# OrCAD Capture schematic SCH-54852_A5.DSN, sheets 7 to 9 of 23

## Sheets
7 C-15 M.2: size C
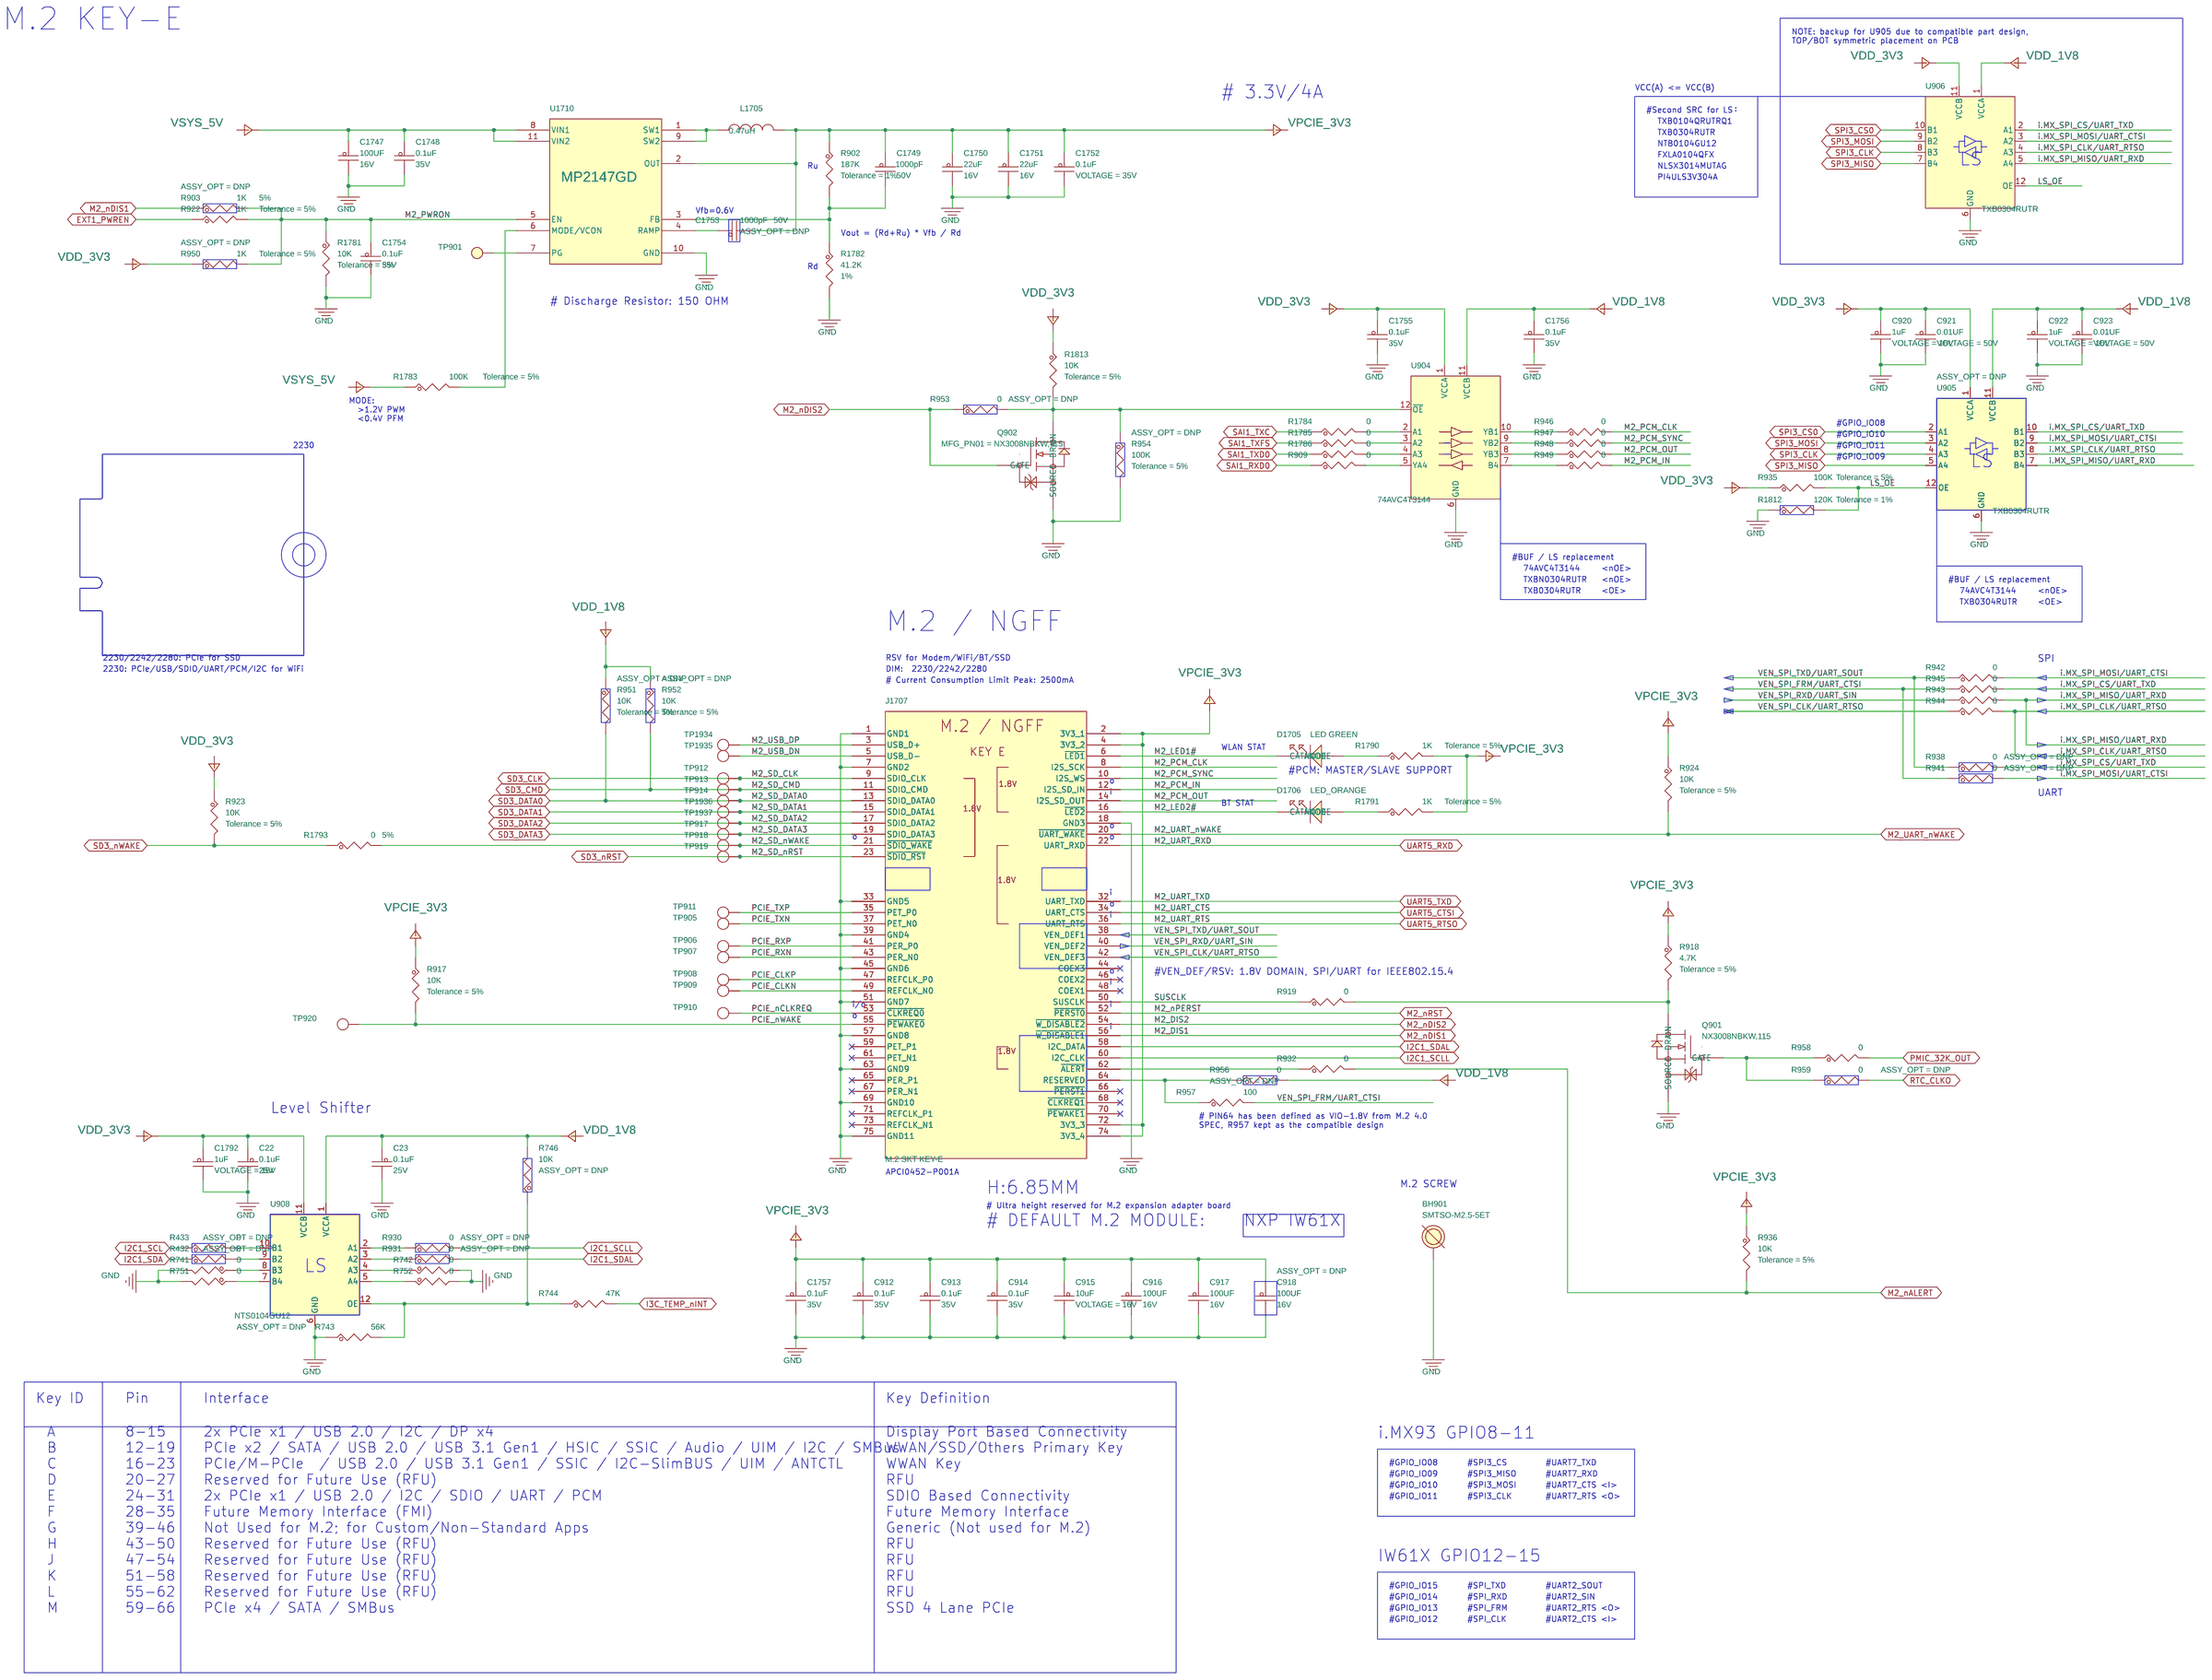
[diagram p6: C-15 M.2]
8 C-14 ENET1: size C
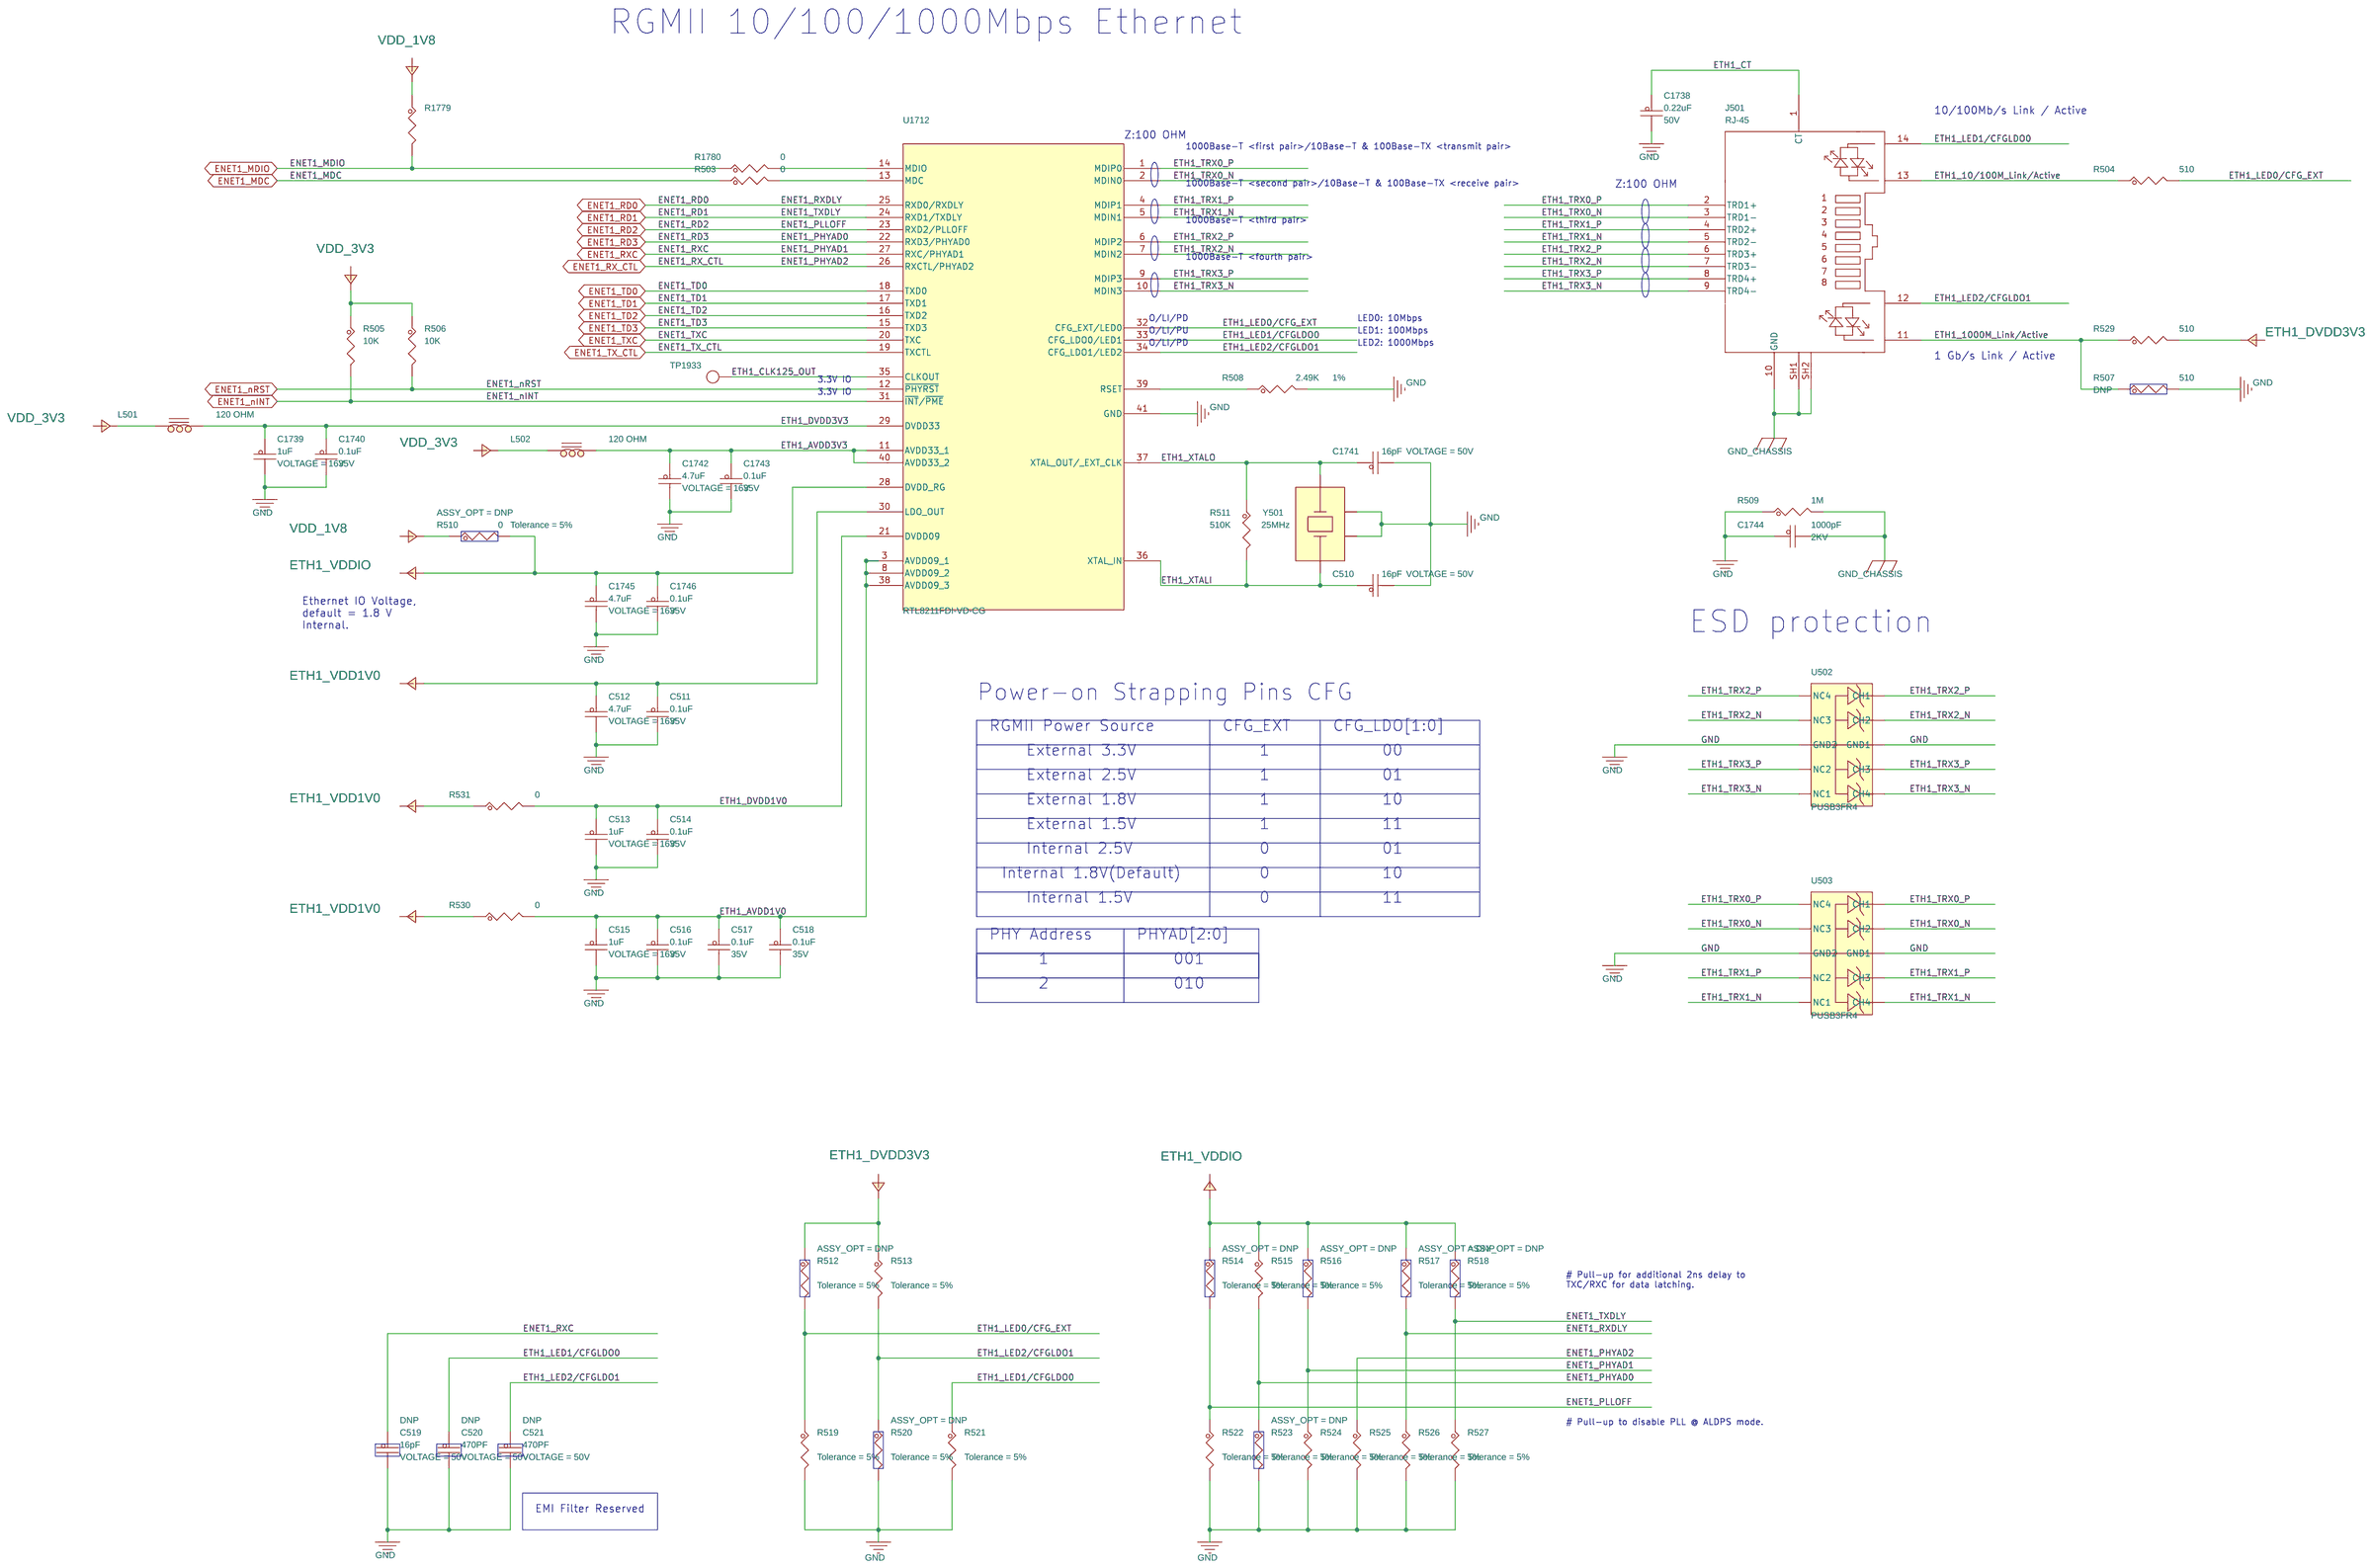
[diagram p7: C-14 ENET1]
9 C-13 USB1 C: size C
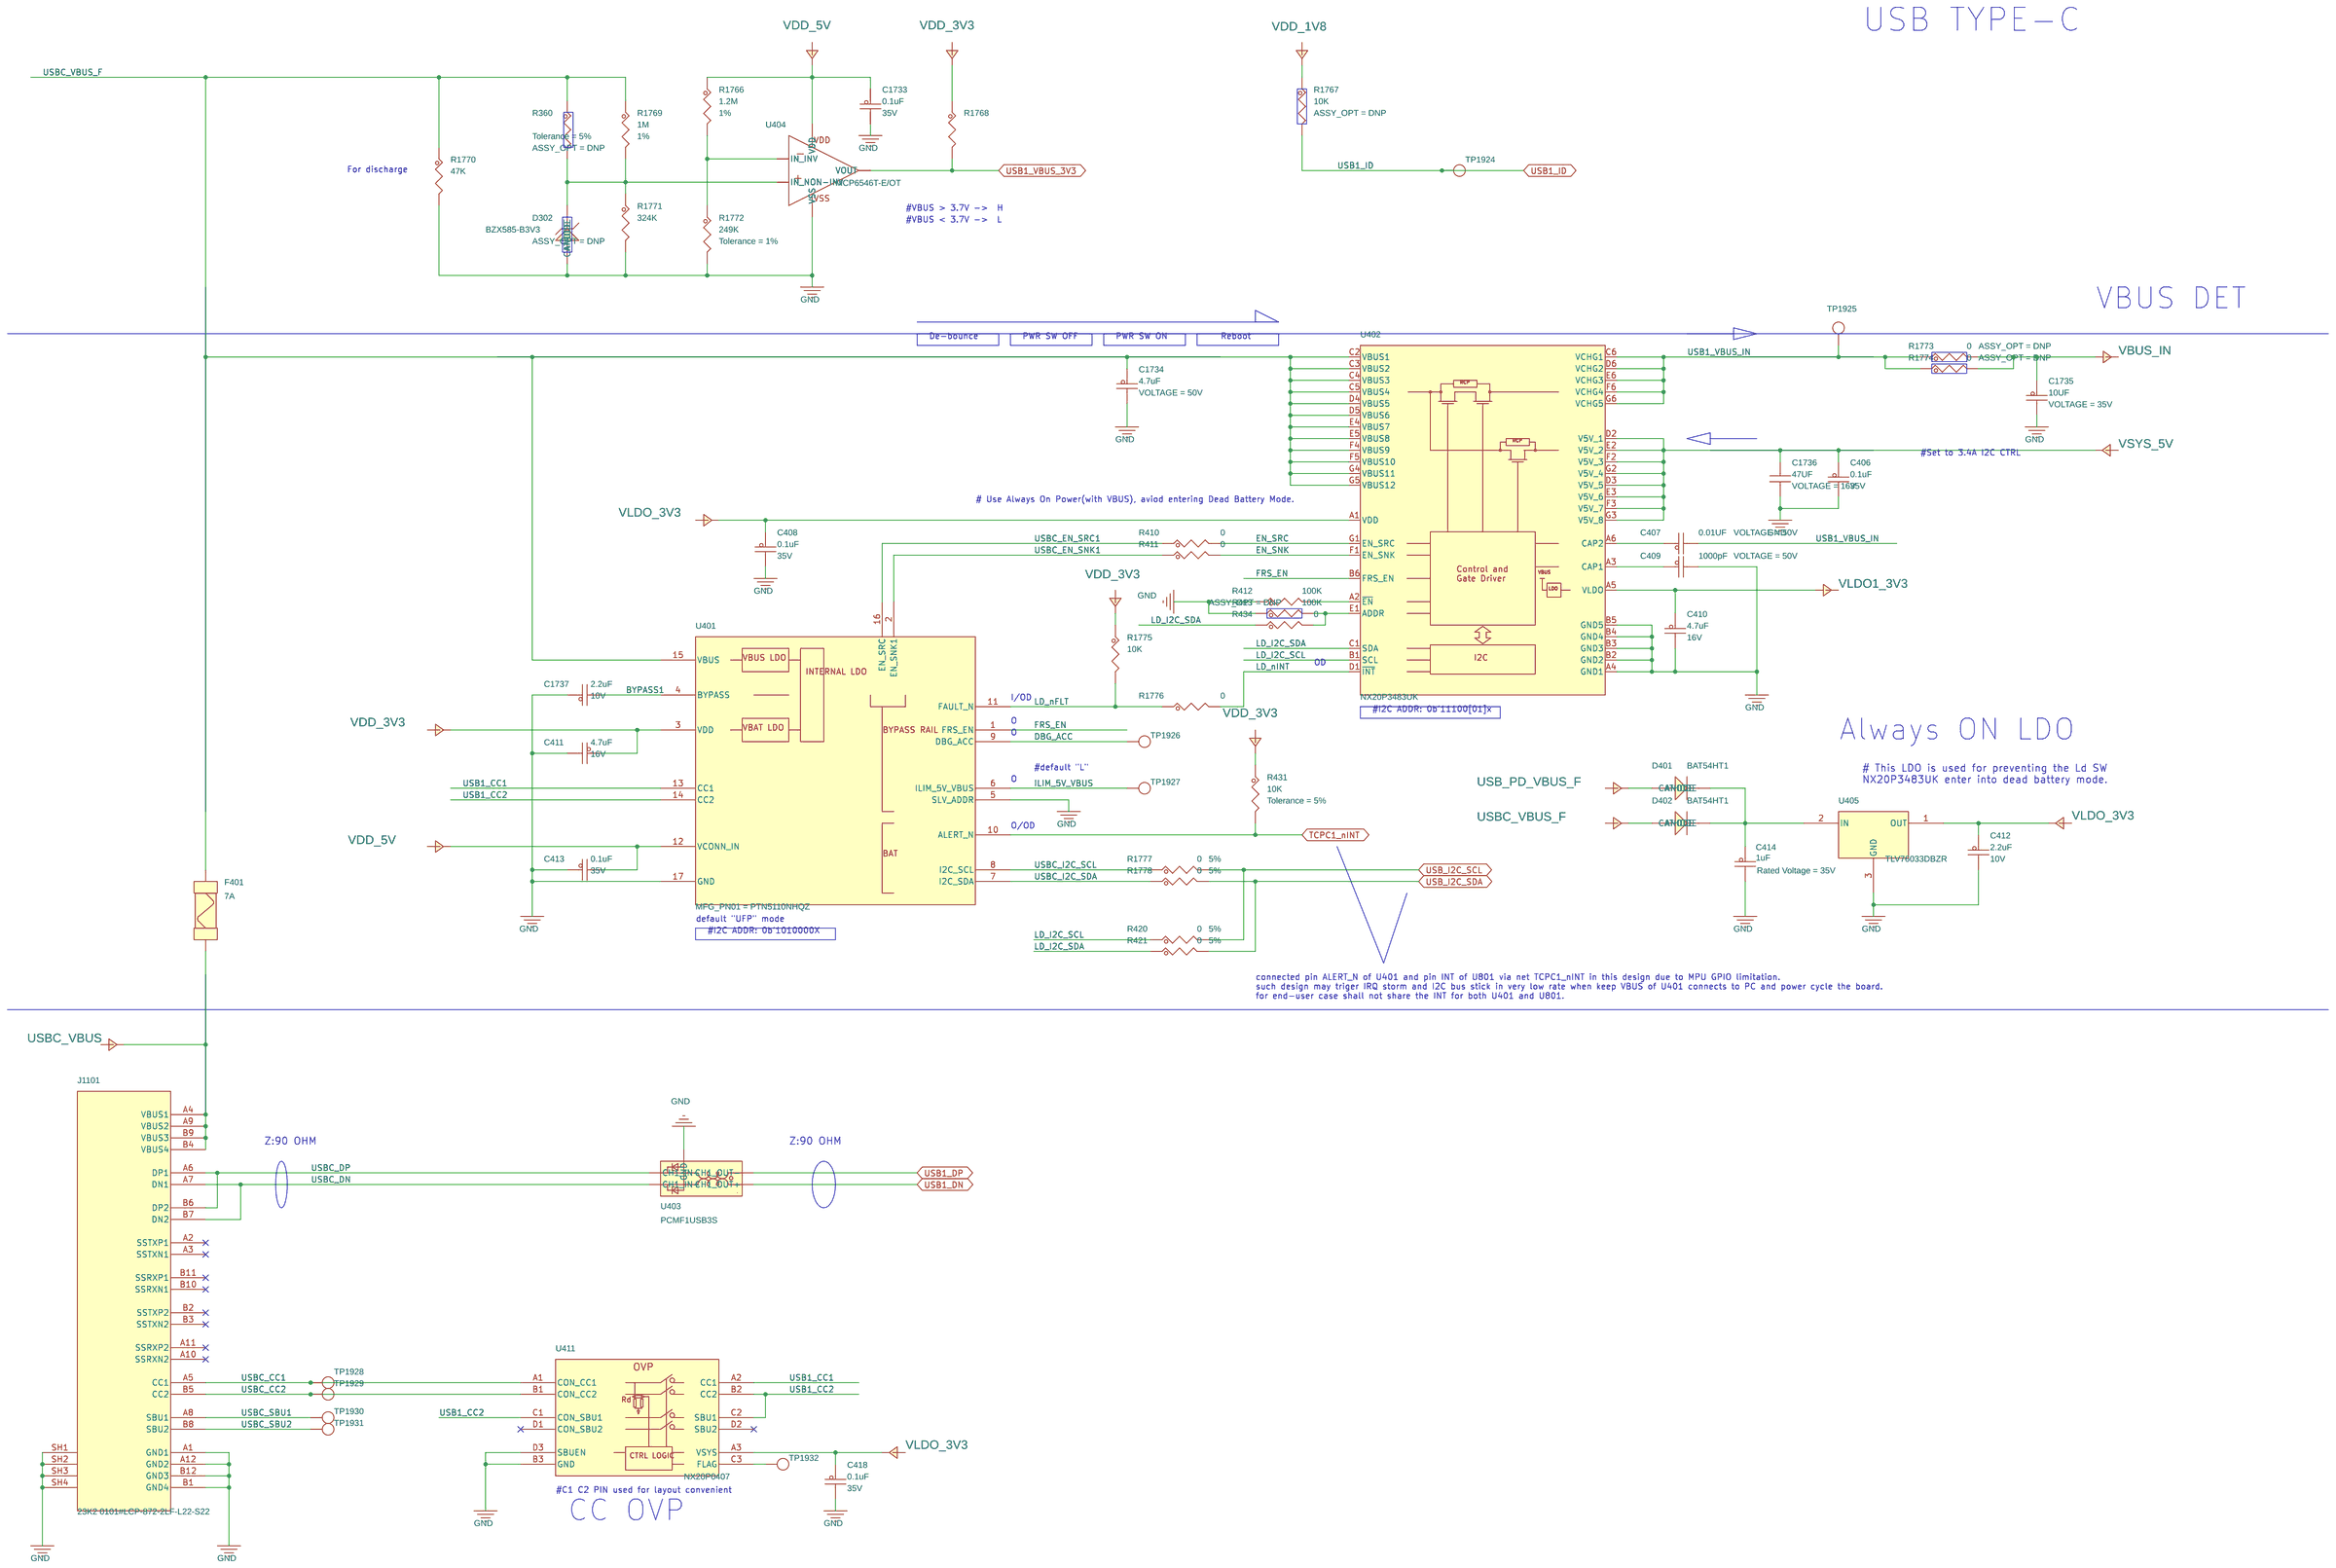
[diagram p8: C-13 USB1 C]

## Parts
sheet C-13 USB1 C
C406  0.1uF  [CC0402_25]
C407  0.01UF  [0402_CC]
C408  0.1uF  [CC0402_25]
C409  1000pF  [0402_CC]
C410  4.7uF  [CC0603_OV]
C411  4.7uF  [CC0603_OV]
C412  2.2uF  [0402_CC]
C413  0.1uF  [CC0402_25]
C414  1uF  [CC0603_OV]
C418  0.1uF  [CC0402_25]
C1733  0.1uF  [CC0402_25]
C1734  4.7uF  [CC1210]
C1735  10UF  [CC1210]
C1736  47UF  [CC1210]
C1737  2.2uF  [0402_CC]
D302  BZX585-B3V3  [sod523]
D401  BAT54HT1  [SOD323]
D402  BAT54HT1  [SOD323]
F401  7A  [fuse_3p4x1p8]
J1101  23K2 0101#LCP-872-2LF-L22-S22  [con24_usb_typec_ra_smt_th_2p2l]
R360  4.7K  [RC0402_25]
R410  0  [0402_CC]
R411  0  [0402_CC]
R412  100K  [0402_CC]
R413  100K  [0402_CC]
R420  0  [0402_CC]
R421  0  [0402_CC]
R431  10K  [0402_CC]
R434  0  [0402_CC]
R1766  1.2M  [0402_CC]
R1767  10K  [0402_CC]
R1768  1K  [0402_CC]
R1769  1M  [0402_CC]
R1770  47K  [0603_CC]
R1771  324K  [0402_CC]
R1772  249K  [0402_CC]
R1773  0  [0805_CC]
R1774  0  [0805_CC]
R1775  10K  [0402_CC]
R1776  0  [0402_CC]
R1777  0  [0402_CC]
R1778  0  [0402_CC]
TP1924  TPAD_020  [tpad_020]
TP1925  TPAD_050  [TPAD_050]
TP1926  TPAD_020  [tpad_020]
TP1927  TPAD_020  [tpad_020]
TP1928  TPAD_020  [tpad_020]
TP1929  TPAD_020  [tpad_020]
TP1930  TPAD_020  [tpad_020]
TP1931  TPAD_020  [tpad_020]
TP1932  TPAD_020  [tpad_020]
U401  PTN5110  [hx2qfn16_0p4_2p7x2p7]
U402  NX20P3483UK  [wlcsp42_0p4_2p94x2p54_smdp]
U403  PCMF1USB3S  [wlcsp5_0p4_0p82x1p22]
U404  MCP6546T-E/OT  [sot23-5]
U405  TLV76033DBZR  [SOT-23]
U411  NX20P0407  [wlcsp12_0p4_1p3x1p7mm_smdp]
sheet C-14 ENET1
C510  16pF  [0402_CC]
C511  0.1uF  [CC0402_25]
C512  4.7uF  [CC0603_OV]
C513  1uF  [CC0402_25]
C514  0.1uF  [CC0402_25]
C515  1uF  [CC0402_25]
C516  0.1uF  [CC0402_25]
C517  0.1uF  [CC0402_25]
C518  0.1uF  [CC0402_25]
C519  16pF  [0402_CC]
C520  470PF  [0402_CC]
C521  470PF  [0402_CC]
C1738  0.22uF  [0402_CC]
C1739  1uF  [CC0402_25]
C1740  0.1uF  [CC0402_25]
C1741  16pF  [0402_CC]
C1742  4.7uF  [CC0603_OV]
C1743  0.1uF  [CC0402_25]
C1744  1000pF  [1206_CC]
C1745  4.7uF  [CC0603_OV]
C1746  0.1uF  [CC0402_25]
J501  RJ-45  [con_rj45_10_2led_th]
L501  120 OHM  [IND_0603]
L502  120 OHM  [IND_0603]
R503  0  [0402_CC]
R504  510  [0402_CC]
R505  10K  [0402_CC]
R506  10K  [0402_CC]
R507  510  [0402_CC]
R508  2.49K  [0402_CC]
R509  1M  [1206_CC]
R510  0  [0402_CC]
R511  510K  [0402_CC]
R512  4.7K  [RC0402_25]
R513  4.7K  [RC0402_25]
R514  4.7K  [RC0402_25]
R515  4.7K  [RC0402_25]
R516  4.7K  [RC0402_25]
R517  4.7K  [RC0402_25]
R518  4.7K  [RC0402_25]
R519  4.7K  [RC0402_25]
R520  4.7K  [RC0402_25]
R521  4.7K  [RC0402_25]
R522  4.7K  [RC0402_25]
R523  4.7K  [RC0402_25]
R524  4.7K  [RC0402_25]
R525  4.7K  [RC0402_25]
R526  4.7K  [RC0402_25]
R527  4.7K  [RC0402_25]
R529  510  [0402_CC]
R530  0  [0603_CC]
R531  0  [0603_CC]
R1779  1.5K  [0402_CC]
R1780  0  [0402_CC]
TP1933  TPAD_020  [tpad_020]
U502  PUSB3FR4  [xson10_0p5_1p1x2p6mm]
U503  PUSB3FR4  [xson10_0p5_1p1x2p6mm]
U1712  RTL8211FDI-VD-CG  [qfn40_0p4_5x5mm]
Y501  25MHz  [xtl4_2p5x2mm_sm]
sheet C-15 M.2
BH901  SMTSO-M2.5-5ET  [mh244-166t_202h]
C22  0.1uF  [CC0402_25]
C23  0.1uF  [CC0402_25]
C912  0.1uF  [CC0402_25]
C913  0.1uF  [CC0402_25]
C914  0.1uF  [CC0402_25]
C915  10uF  [CC0603_OV]
C916  100UF  [1210_CC]
C917  100UF  [1210_CC]
C918  100UF  [1210_CC]
C920  1uF  [CC0402_25]
C921  0.01UF  [0402_CC]
C922  1uF  [CC0402_25]
C923  0.01UF  [0402_CC]
C1747  100UF  [1210_CC]
C1748  0.1uF  [CC0402_25]
C1749  1000pF  [0402_CC]
C1750  22uF  [CC0805_OV]
C1751  22uF  [CC0805_OV]
C1752  0.1uF  [CC0402_25]
C1753  1000pF  [0402_CC]
C1754  0.1uF  [CC0402_25]
C1755  0.1uF  [CC0402_25]
C1756  0.1uF  [CC0402_25]
C1757  0.1uF  [CC0402_25]
C1792  1uF  [0402_CC]
D1705  LED GREEN  [LED_0603]
D1706  LED_ORANGE  [led_0603_11mil]
J1707  M.2 SKT KEY-E  [con_75_0p5_22x9_ra1]
L1705  0.47uH  [ind_sph2520]
Q901  NX3008NBKW,115  [sc70_3]
Q902  NX3008NBKW,115  [sc70_3]
R432  0  [rc0402_25]
R433  0  [rc0402_25]
R741  0  [rc0402_25]
R742  0  [rc0402_25]
R743  56K  [RC0402_25]
R744  47K  [RC0402_25]
R746  10K  [0402_CC]
R751  0  [rc0402_25]
R752  0  [rc0402_25]
R902  187K  [0402_CC]
R903  1K  [0402_CC]
R909  0  [0402_CC]
R917  10K  [0402_CC]
R918  4.7K  [RC0402_25]
R919  0  [0402_CC]
R922  1K  [0402_CC]
R923  10K  [0402_CC]
R924  10K  [0402_CC]
R930  0  [0402_CC]
R931  0  [0402_CC]
R932  0  [0402_CC]
R935  100K  [0402_CC]
R936  10K  [0402_CC]
R938  0  [0402_CC]
R941  0  [0402_CC]
R942  0  [0402_CC]
R943  0  [0402_CC]
R944  0  [0402_CC]
R945  0  [0402_CC]
R946  0  [0402_CC]
R947  0  [0402_CC]
R948  0  [0402_CC]
R949  0  [0402_CC]
R950  1K  [0402_CC]
R951  10K  [0402_CC]
R952  10K  [0402_CC]
R953  0  [0402_CC]
R954  100K  [0402_CC]
R956  0  [0402_CC]
R957  100  [RC0402_25]
R958  0  [0402_CC]
R959  0  [0402_CC]
R1781  10K  [0402_CC]
R1782  41.2K  [RC0402_25]
R1783  100K  [0402_CC]
R1784  0  [0402_CC]
R1785  0  [0402_CC]
R1786  0  [0402_CC]
R1790  1K  [0402_CC]
R1791  1K  [0402_CC]
R1793  0  [0402_CC]
R1812  120K  [0402_CC]
R1813  10K  [0402_CC]
TP901  TP_35MIL  [testpoint_35mil]
TP905  TPAD_020  [tpad_020]
TP906  TPAD_020  [tpad_020]
TP907  TPAD_020  [tpad_020]
TP908  TPAD_020  [tpad_020]
TP909  TPAD_020  [tpad_020]
TP910  TPAD_020  [tpad_020]
TP911  TPAD_020  [tpad_020]
TP912  TPAD_020  [tpad_020]
TP913  TPAD_020  [tpad_020]
TP914  TPAD_020  [tpad_020]
TP917  TPAD_020  [tpad_020]
TP918  TPAD_020  [tpad_020]
TP919  TPAD_020  [tpad_020]
TP920  TPAD_020  [tpad_020]
TP1934  TPAD_020  [tpad_020]
TP1935  TPAD_020  [tpad_020]
TP1936  TPAD_020  [tpad_020]
TP1937  TPAD_020  [tpad_020]
U904  74AVC4T3144  [xqfn12_0p4_1p8x2p1]
U905  TXB0304RUTR  [uqfn12_1p7x2mm]
U906  TXB0304RUTR  [uqfn12_1p7x2mm]
U908  NTS0104GU12  [xqfn12_0p4_1p8x2p1]
U1710  MP2147GD  [qfn12_0p5_2x3mm_ep]

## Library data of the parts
C406 C408 C413 C418 C511 C514 C516-C518 C912-C914 C1733 C1740 C1743 C1746 C1748 C1752 C1754 C1757 = CAP_NP: CAP CER 0.1UF 35V 10% X5R 0402; AGILE_PN: 150-78506; CAD_APPROVED: Yes; FPLIST: CC0402_25,CC0402_HD,0402_CC,capc0402_l; HEIGHT: 0.55MM; MFG_NAME01: TAIYO YUDEN; MFG_PN01: GMK105BJ104KV-F; ROHS: Yes; Tolerance: 10%; VOLTAGE: 35V
C407 = CAP_NP: CAP CER 0.01UF 50V 10% X7R 0402; AGILE_PN: 150-30114; CAD_APPROVED: Yes; FPLIST: CC0402_25,CC0402_HD,0402_CC,capc0402_l; HEIGHT: 0.55 MM; MFG_NAME01: MURATA; MFG_PN01: GRM155R71H103KA88D; ROHS: Yes; Tolerance: 10%; VOLTAGE: 50V
C409 = CAP_NP: CAP CER 1000PF 50V 5% C0G 0402; AGILE_PN: 150-76334; CAD_APPROVED: Yes; FPLIST: CC0402_25,CC0402_HD,0402_CC,capc0402_l; HEIGHT: 0.55MM; MFG_NAME01: MURATA; MFG_PN01: GRM1555C1H102JA01D; Package Size: 0402; Package Type: 180mm Paper Tape; ROHS: Yes; Tolerance: 5%; VOLTAGE: 50V
C410 C411 C512 C1742 C1745 = CAP_NP: CAP CER 4.7uF 16V 10% X5R 0603; AGILE_PN: 150-80061; CAD_APPROVED: Yes; FPLIST: CC0603_OV,CC0603,cc0603_0805_nsp,0603_CC_NSP; HEIGHT: 0.95MM; MFG_NAME01: MURATA; MFG_PN01: GRM188R61C475KE11D; ROHS: Yes; Temp Range: -55°C to + 85°C; VOLTAGE: 16V
C412 C1737 = CAP_NP: CAP CER 2.2uF 10V 10% X5R 0402; AGILE_PN: 150-78974; CAD_APPROVED: Yes; FPLIST: CC0402_25,CC0402_HD,0402_CC,capc0402_l; HEIGHT: 0.55 MM; MFG_NAME01: TDK; MFG_PN01: C1005X5R1A225K; Package Size: 0402; ROHS: Yes; Tolerance: 10%; VOLTAGE: 10V
C414 = CAP_NP: CAP CER 1uF 35V 10% X7R 0603; AGILE_PN: 150-81157; CAD_APPROVED: Yes; FPLIST: CC0603_OV,CC0603,0603_CC; HEIGHT: 0.9MM; MFG_NAME01: TDK; MFG_PN01: C1608X7R1V105K080AC; Package Size: 0603 (1608 Metric); Package Type: Surface Mount, MLCC; ROHS: Yes; Rated Voltage: 35V; Temp Range: -55C to +125C; Tolerance: 10%
C1734 = CAP_NP: CAP CER 4.7UF 50V 10% X7R 1210; AGILE_PN: 150-76570; CAD_APPROVED: Yes; FPLIST: CC1210,1210_CC; HEIGHT: 2.7MM; MFG_NAME01: YAGEO AMERICA; MFG_PN01: CC1210KKX7R9BB475; ROHS: Yes; Tolerance: 10%; VOLTAGE: 50V
C1735 = CAP_NP: CAP CER 10UF 35V 20% X5R 1210; AGILE_PN: 150-80339; CAD_APPROVED: Yes; FPLIST: CC1210,1210_CC; HEIGHT: 2.1MM; MFG_NAME01: KEMET; MFG_PN01: C1210C106M6PACTU; Package Size: 1210; Package Type: SMD; ROHS: Yes; Temp Range: -55° C to +85° C; Tolerance: 20%; VOLTAGE: 35V
C1736 = MOT_CAP: CAP CER 47UF 16V 10% X5R 1210; AGILE_PN: 150-75908; CAD_APPROVED: Yes; FPLIST: CC1210,1210_CC; HEIGHT: 2.7 mm; MFG_NAME01: YAGEO AMERICA; MFG_PN01: CC1210KKX5R7BB476; ROHS: Yes; Tolerance: 10%; VOLTAGE: 16V
D302 = ZDIODE: DIODE ZNR 0.3W 3.3V 200mA AEC-Q101 SOD-523; AGILE_PN: 480-79870; ASSY_OPT: DNP; CAD_APPROVED: Yes; HEIGHT: 0.65MM; MFG_NAME01: NEXPERIA; ROHS: Yes; Temp Range: -65°C to +150°C; Temp_Range: -65°C to +150°C
D401 D402 = DIODE: DIODE SCH 30V 200MA -- SOD323; AGILE_PN: 480-30039; CAD_APPROVED: Yes; HEIGHT: 1.15MM; MFG_NAME01: ON SEMICONDUCTOR; MFG_PN01: BAT54HT1G
F401 = FUSE: FUSE HIGH I2T 7A 32V 1206; AGILE_PN: 510-77913; CAD_APPROVED: Yes; HEIGHT: 0.8639MM; MFG_NAME01: LITTELFUSE; MFG_PN01: 0440007.WR; ROHS: Yes
J1101 = USB24_TYPEC_SH4: CON 24 USB TYPE C RA SHLD HYBRID SMT-TH 0.5MM SP 145H AU 87L; AGILE_PN: 211-83409; CAD_APPROVED: Yes; HEIGHT: 3.67MM; MFG_NAME01: ANYTRONIC CORPORATION LIMITED; MFG_PN01: 23K20101#LCP-872-2LF-L22-S22; ROHS: Yes; Temp Range: -55°C to +105°C
R360 R512 R514 R516-R518 R520 R523 = RES: RES MF 4.7K 1/16W 5% 0402; AGILE_PN: 470-75626; ASSY_OPT: DNP; CAD_APPROVED: Yes; FPLIST: RC0402_25,RC0402_HD,0402_CC,RC0402_X2; HEIGHT: 0.41mm; MFG_NAME01: NIC COMPONENTS CORP; MFG_PN01: NRCL04J472TRF; ROHS: Yes; Tolerance: 5%
R410 R411 R420 R421 R434 R503 R909 R919 R932 R942-R949 R958 R1776-R1778 R1780 R1784-R1786 R1793 = RES: RES MF ZERO OHM 1/16W 5% 0402; AGILE_PN: 470-75394; CAD_APPROVED: Yes; FPLIST: RC0402_25,RC0402_HD,RC0402_X2,0402_CC; HEIGHT: 0.45 MM; MFG_NAME01: ROHM; MFG_PN01: MCR01MZPJ000; ROHS: Yes; Tolerance: 5%; VOLTAGE: 1/16W
R412 R935 R1783 = RES: RES MF 100K 1/16W 5% 0402; AGILE_PN: 470-75597; CAD_APPROVED: Yes; FPLIST: RC0402_25,RC0402_HD,0402_CC; HEIGHT: 0.40 MM; MFG_NAME01: VENKEL COMPANY; MFG_PN01: CR0402-16W-104JT; ROHS: Yes; Temp Range: -55C to +155C; Temp_Range: -55C to +155C; Tolerance: 5%; VOLTAGE: 50V
R413 R954 = RES: RES MF 100K 1/16W 5% 0402; AGILE_PN: 470-75597; ASSY_OPT: DNP; CAD_APPROVED: Yes; FPLIST: RC0402_25,RC0402_HD,0402_CC; HEIGHT: 0.40 MM; MFG_NAME01: VENKEL COMPANY; MFG_PN01: CR0402-16W-104JT; ROHS: Yes; Temp Range: -55C to +155C; Temp_Range: -55C to +155C; Tolerance: 5%; VOLTAGE: 50V
R431 R505 R506 R917 R923 R924 R936 R1775 R1781 R1813 = RES: RES MF 10K 1/16W 5% 0402; AGILE_PN: 470-75557; CAD_APPROVED: Yes; FPLIST: RC0402_25,RC0402_HD,0402_CC; HEIGHT: 0.4 MM; MFG_NAME01: VISHAY INTERTECHNOLOGY; MFG_PN01: CRCW040210K0JNED; ROHS: Yes; Tolerance: 5%
R1766 = RES: RES MF 1.2M  1/10W 1% AEC-Q200 0402; AGILE_PN: 470-31182; CAD_APPROVED: Yes; FPLIST: RC0402_25,RC0402_HD,0402_CC; HEIGHT: 0.40 MM; MFG_NAME01: KOA SPEER; MFG_PN01: RK73H1ETTP1204F; ROHS: Yes; Temp Range: -55C to +155C; Temp_Range: -55C to +155C; Tolerance: 1%; VOLTAGE: 50V
R746 R951 R952 R1767 = RES: RES MF 10K 1/16W 5% 0402; AGILE_PN: 470-75557; ASSY_OPT: DNP; CAD_APPROVED: Yes; FPLIST: RC0402_25,RC0402_HD,0402_CC; HEIGHT: 0.4 MM; MFG_NAME01: VISHAY INTERTECHNOLOGY; MFG_PN01: CRCW040210K0JNED; ROHS: Yes; Tolerance: 5%
R1768 = RES: RES MF 1.0K 1/16W 5% 0402; AGILE_PN: 470-75555; CAD_APPROVED: Yes; FPLIST: RC0402_25,RC0402_HD,RC0402_X2,0402_CC,CAPC0402_L; HEIGHT: 0.41mm; MFG_NAME01: VISHAY INTERTECHNOLOGY; MFG_PN01: CRCW04021K00JNED; ROHS: Yes; TOL: 5%; Tolerance: 5%
R1769 = RES: RES MF 1M 1/16W 1% 0402; AGILE_PN: 470-80575; CAD_APPROVED: Yes; FPLIST: RC0402_25,RC0402_HD,0402_CC; HEIGHT: 0.4MM; MFG_NAME01: BOURNS; MFG_PN01: CR0402-FX-1004GLF; ROHS: Yes; Tolerance: 1%
R1770 = RES: RES MF 47K 1/10W 5% 0603; AGILE_PN: 470-75849; CAD_APPROVED: Yes; FPLIST: RC0603_OV,RC0603,0603_CC; HEIGHT: 0.55 MM; MFG_NAME01: VENKEL COMPANY; MFG_PN01: CR0603-10W-473JT; ROHS: Yes; Tolerance: 5%
R1771 = RES: RES MF 324K 1/16W 1% 0402; AGILE_PN: 470-76121; CAD_APPROVED: Yes; FPLIST: RC0402_25,RC0402_HD,0402_CC; HEIGHT: 0.40 MM; MFG_NAME01: PANASONIC; MFG_PN01: ERJ2RKF3243X; ROHS: Yes; Tolerance: 1%
R1772 = RES: RES MF 249K 1/10W 1% AEC-Q200 0402; AGILE_PN: 470-31103; CAD_APPROVED: Yes; FPLIST: RC0402_25,RC0402_HD,0402_CC; HEIGHT: 0.40 MM; MFG_NAME01: KOA SPEER; MFG_PN01: RK73H1ETTP2493F; ROHS: Yes; Temp Range: -55C to +155C; Temp_Range: -55C to +155C; Tolerance: 1%
R1773 R1774 = RES: RES MF ZERO OHM JUMPER 1/2W AEC-Q200 0805; AGILE_PN: 470-81272; ASSY_OPT: DNP; CAD_APPROVED: Yes; FPLIST: RC0805_OV,RC0805,0805_CC; HEIGHT: 0.6MM; MFG_NAME01: VISHAY INTERTECHNOLOGY; MFG_PN01: CRCW08050000Z0EAHP; ROHS: Yes; Temp Range: -55 °C to +155 °C; VOLTAGE: 150V
TP905-TP914 TP917-TP920 TP1924 TP1926-TP1937 = TESTLOOP: TEST POINT PAD 0.5MM DIA SMT, NO PART TO ORDER; AGILE_PN: 211-77484; ASSY_OPT: DNP; CAD_APPROVED: Yes; HEIGHT: 0.1MM; ROHS: Yes
TP1925 = TESTLOOP: TEST POINT PAD 50MIL DIA SMT, NO PART TO ORDER; AGILE_PN: 211-76644; ASSY_OPT: DNP; CAD_APPROVED: Yes; HEIGHT: 0.1MM; MFG_NAME01: NOTACOMPONENT; MFG_PN01: NOTACOMPONENT; ROHS: Yes
U401 = PTN5110_QFN16: IC USB PD PHY 1PORT 2.7-5.5V HX2QFN16; AGILE_PN: 315-81118; CAD_APPROVED: Yes; HEIGHT: 0.4MM; MFG_NAME01: NXP SEMICONDUCTORS; MFG_PN01: PTN5110NHQZ; ROHS: Yes; Temp Range: ¨C40C to +85C; Temp_Range: ¨C40C to +85C; VOLTAGE: 2.7-5.5V
U402 = NX20P3483UK_42P: IC USB PD/TYPE-C PWR Sink/Source Combo SW 5A 2.8-20V WLCSP42; AGILE_PN: 315-81752; CAD_APPROVED: Yes; HEIGHT: 0.565MM; MFG_NAME01: NXP SEMICONDUCTORS; PRE_APN: 315-81752; ROHS: Yes; Temp_Range: -40C to +85C
U403 = PESD1USB30_5P: IC EMI FILTER ESD PROTECTION 15kV/LINE WLCSP5; 3D_Mechanical_Footprint_File: http://fcl.am.freescale.net/ALLEGRO/step/wlcsp5_0p4_0p82x1p22.STEP; AGILE_PN: 315-84061; CAD_APPROVED: Yes; HEIGHT: 0.6MM; MFG_NAME01: NEXPERIA; MFG_PN01: PCMF1USB3SZ; ROHS: Yes
U404 = OPAMP_5P: IC COMP MICRO POWER RAIL-TO-RAIL 1.6-5.5V SOT23-5; 3D_Mechanical_Footprint_File: http://fcl.am.freescale.net/ALLEGRO/step/sot23-5.STEP; AGILE_PN: 315-10155; CAD_APPROVED: Yes; HEIGHT: 1.45 MM; MFG_NAME01: MICROCHIP TECHNOLOGY INC; ROHS: NULL; Temp Range: -40  °C to +125 °C; VOLTAGE: 1.6-5.5V
U405 = LM3480IM3: IC LIN VREG 3.3V 100mA 30V SOT23; AGILE_PN: 315-83524; CAD_APPROVED: Yes; HEIGHT: 1.12 MM; MFG_NAME01: Texas Instruments; Package Size: SOT-23-3; ROHS: Yes; Temp Range: -40  °C - 125 °C
U411 = NX20P0407_WLCSP12_A: IC USB TYPE C PROTECTION +15KV/+8KV ESD WLCSP12; AGILE_PN: TMP-WF-31350; CAD_APPROVED: Yes; HEIGHT: 0.565 MM; MFG_NAME01: NXP SEMICONDUCTORS; PRE_APN: 312-81846; ROHS: Yes; Temp Range: -40C to +85C; VOLTAGE: +15KV/+8KV
C510 C1741 = CAP_NP: CAP CER 16pF 50V 1% C0G 0402; AGILE_PN: 150-80485; CAD_APPROVED: Yes; FPLIST: CC0402_25,CC0402_HD,0402_CC,capc0402_l; HEIGHT: 0.6MM; MFG_NAME01: AVX; MFG_PN01: 04025U160FAT2A; PRIORITY_PN: 021-00234; Package Size: 0402; ROHS: Yes; ROOM: RGMII_PHY; SIGNAL_MODEL: DEFAULT_CAPACITOR_22pF_2_1; Temp Range: -55°C to +125°C; Temp_Range: -55°C to 125°C; Tolerance: 1%; VOLTAGE: 50V; WVDC: 50V
C513 C515 C920 C922 C1739 = CAP_NP: CAP CER 1uF 16V 10% X5R 0402; AGILE_PN: 150-78973; CAD_APPROVED: Yes; FPLIST: CC0402_25,CC0402_HD,0402_CC,capc0402_l; HEIGHT: 0.55 MM; MFG_NAME01: YAGEO; MFG_PN01: CC0402KRX5R7BB105; ROHS: Yes; SIGNAL_MODEL: DEFAULT_CAPACITOR_1e+06pF_2_1; TOL: 10%; Tolerance: 10%; VOLTAGE: 16V; voltage rating: 10V
C519 = CAP_NP: CAP CER 16pF 50V 1% C0G 0402; AGILE_PN: 150-80485; ASSY_OPT: DNP; CAD_APPROVED: Yes; FPLIST: CC0402_25,CC0402_HD,0402_CC,capc0402_l; HEIGHT: 0.6MM; MFG_NAME01: AVX; MFG_PN01: 04025U160FAT2A; PRIORITY_PN: 021-00234; Package Size: 0402; ROHS: Yes; ROOM: RGMII_PHY; SIGNAL_MODEL: DEFAULT_CAPACITOR_22pF_2_1; Temp Range: -55°C to +125°C; Temp_Range: -55°C to 125°C; Tolerance: 1%; VOLTAGE: 50V; WVDC: 50V
C520 C521 = CAP_NP: CAP CER 470PF 50V 10% X7R 0402; AGILE_PN: 150-75452; ASSY_OPT: DNP; CAD_APPROVED: Yes; FPLIST: CC0402_25,CC0402_HD,0402_CC; HEIGHT: 0.55MM; MFG_NAME01: WALSIN TECHNOLOGY CORP.; MFG_PN01: 0402B471K500CT; PRIORITY_PN: 021-00340; ROHS: Yes; ROOM: RGMII_PHY; SIGNAL_MODEL: DEFAULT_CAPACITOR_470pF_2_1; Tolerance: 10%; VOLTAGE: 50V; WVDC: 50V
C1738 = CAP_NP: CAP CER 0.22uF 50V 10% X5R 0402; AGILE_PN: 150-79999; CAD_APPROVED: Yes; EN: 102-1-01816; FPLIST: CC0402_25,CC0402_HD,0402_CC,capc0402_l; HEIGHT: 0.55MM; MFG_NAME01: TAIYO YUDEN; MFG_PN01: UMK105BJ224KV-F; Package Size: 0402; ROHS: Yes; TOL: 10%; Temp Range: -55°C to +85°C; Tolerance: 10%; VOLTAGE: 50V
C1744 = CAP_NP: CAP CER 1000pF 2KV 10% X7R 1206; AGILE_PN: 150-79462; CAD_APPROVED: Yes; FPLIST: CC1206_OV,CC1206,1206_CC; HEIGHT: 1.52MM; MFG_NAME01: AVX; MFG_PN01: 1206GC102KAT1A; Package Size: 1206; ROHS: Yes; VOLTAGE: 2KV; WVDC: 2KV
J501 = RJ45_2_DUAL_LED_10P: CON 2X5 RJ-45 DUAL-LED SHLD RA TH 1.27MM SP 549H AU 120L; AGILE_PN: 210-81462; CAD_APPROVED: Yes; EN: 201-2-00061; HEIGHT: 13.95MM; MFG_NAME01: WURTH ELEKTRONIK EISOS GMBH & CO. KG (ELECTRONIC & ELECTROMEHANICAL COMP); MFG_PN01: 7499111446; ROHS: Yes; Temp Range: -40DegC to +85DegC; Temp_Range: -40DegC to +85DegC
L501 L502 = BEAD_0: IND FER BEAD 120OHM@100MHZ 2A 25% 0603; AGILE_PN: 180-78419; CAD_APPROVED: Yes; FPLIST: IND_0603,0603_CC; HEIGHT: 0.95MM; MFG_NAME01: MURATA; MFG_PN01: BLM18PG121SN1D; ROHS: Yes
R504 R529 = RES: RES MF 510 OHM 1/16W 1% 0402; AGILE_PN: 470-80835; CAD_APPROVED: Yes; FPLIST: RC0402_25,RC0402_HD,0402_CC; HEIGHT: 0.4MM; MFG_NAME01: WALSIN TECHNOLOGY CORP.; MFG_PN01: WR04X5100FTL; ROHS: Yes; Tolerance: 1%
R507 = RES: RES MF 510 OHM 1/16W 1% 0402; AGILE_PN: 470-80835; ASSY_OPT: DNP; CAD_APPROVED: Yes; FPLIST: RC0402_25,RC0402_HD,0402_CC; HEIGHT: 0.4MM; MFG_NAME01: WALSIN TECHNOLOGY CORP.; MFG_PN01: WR04X5100FTL; ROHS: Yes; Tolerance: 1%
R508 = RES: RES MF 2.49K  1/10W 1% AEC-Q200 0402; AGILE_PN: 470-30877; CAD_APPROVED: Yes; FPLIST: RC0402_25,RC0402_HD,0402_CC; HEIGHT: 0.40 MM; MFG_NAME01: KOA SPEER; MFG_PN01: RK73H1ETTP2491F; ROHS: Yes; SIGNAL_MODEL: DEFAULT_RESISTOR_2490OHM_2_1; Temp Range: -55C to +155C; Temp_Range: -55C to +155C; Tolerance: 1%; VOLTAGE: 50V
R509 = RES: RES MF 1.0M 1/4W 1% 1206; AGILE_PN: 470-81076; CAD_APPROVED: Yes; FPLIST: RC1206_OV,RC1206,1206_CC; HEIGHT: 0.6MM; MFG_NAME01: VISHAY INTERTECHNOLOGY; MFG_PN01: RCV12061M00FKEA; ROHS: Yes; Tolerance: 1%; VOLTAGE: 500V
R510 R930 R931 R938 R941 R953 R956 R959 = RES: RES MF ZERO OHM 1/16W 5% 0402; AGILE_PN: 470-75394; ASSY_OPT: DNP; CAD_APPROVED: Yes; FPLIST: RC0402_25,RC0402_HD,RC0402_X2,0402_CC; HEIGHT: 0.45 MM; MFG_NAME01: ROHM; MFG_PN01: MCR01MZPJ000; ROHS: Yes; Tolerance: 5%; VOLTAGE: 1/16W
R511 = RES: RES MF 510K 1/16W 5% 0402; AGILE_PN: 470-76166; CAD_APPROVED: Yes; FPLIST: RC0402_25,RC0402_HD,0402_CC; HEIGHT: 0.4 MM; MFG_NAME01: PANASONIC; MFG_PN01: ERJ-2GEJ514X; ROHS: Yes; Tolerance: 5%
R513 R515 R519 R521 R522 R524-R527 R918 = RES: RES MF 4.7K 1/16W 5% 0402; AGILE_PN: 470-75626; CAD_APPROVED: Yes; FPLIST: RC0402_25,RC0402_HD,0402_CC,RC0402_X2; HEIGHT: 0.41mm; MFG_NAME01: NIC COMPONENTS CORP; MFG_PN01: NRCL04J472TRF; ROHS: Yes; Tolerance: 5%
R530 R531 = RES: RES MF ZERO OHM 1/10W -- 0603; AGILE_PN: 470-80866; CAD_APPROVED: Yes; FPLIST: RC0603_OV,RC0603,R603-X2,0603_CC,IND_0603HP_NSP,CC0603_OV_NSP; HEIGHT: 0.6MM; MFG_NAME01: WALSIN TECHNOLOGY CORP.; MFG_PN01: WR06X000PTL; ROHS: Yes; Temp Range: –55 °C to +155 °C
R1779 = RES: RES MF 1.5K 1/16W 1% 0402; AGILE_PN: 470-80487; ASSY_NOTE: 470-76065; CAD_APPROVED: Yes; FPLIST: RC0402_25,RC0402_HD,0402_CC; HEIGHT: 0.4MM; MFG_NAME01: BOURNS; MFG_PN01: CR0402-FX-1501GLF; PRIORITY_PN: 006-00654; ROHS: Yes; ROOM: RGMII_PHY; TOLERANCE: 1%
U502 U503 = DIODE_ESD_4CH_10P_A_1: DIODE ARRAY ESD 3.3V 5A DFN2510A-10; 3D_Mechanical_Footprint_File: http://fcl.am.freescale.net/ALLEGRO/step/xson10_0p5_1p1x2p6mm.step; AGILE_PN: 480-78961; CAD_APPROVED: Yes; HEIGHT: 0.5MM; MFG_NAME01: NEXPERIA; MFG_PN01: PUSB3FR4Z
U1712 = RTL8211FDI-40P: IC XCVR ETH INTEGRATED 10/100/1000MBPS RGMII 3.3V/2.5V/1.8V QFN40; 3D_Mechanical_Footprint_File: ftp://fcl.am.freescale.net/ALLEGRO/step/qfn40_0p4_5x5mm.STEP; AGILE_PN: TMP-CIP-10596; CAD_APPROVED: Yes; HEIGHT: 0.9MM; MFG_NAME01: REALTEK SEMICONDUCTOR; PRE_APN: 312-83499; Package Size: QFN40; ROHS: Yes; Temp Range: -40  °C  +85 °C
Y501 = XTAL_13: XTAL 25MHZ FIXED -- SMT; AGILE_PN: 230-76732; CAD_APPROVED: Yes; HEIGHT: 0.55MM; MFG_NAME01: TXC CORP; MFG_PN01: 8Z 25.000; ROHS: Yes
BH901 = MOUNT_HOLE: FASTENER, STANDOFF M2.5 ROUND FEMALE OD CS L5.13MM; AGILE_PN: 280-77749; CAD_APPROVED: Yes; HEIGHT: 5.13MM; MFG_NAME01: SHENZHEN SINHOO SCIENCE TECHNOLOGY DEVELOPMENT CO.,LTD; ROHS: Yes
C22 C23 = CAP_NP: CAP CER 0.1uF 25V 10% X7R AEC-Q200  0402; 3D_Mechanical_Footprint_File: http://fcl.am.freescale.net/ALLEGRO/step/cc0402_25.STEP; AGILE_PN: 150-81751; CAD_APPROVED: Yes; FPLIST: CC0402_25,CC0402_HD,0402_CC,capc0402_l; HEIGHT: 0.55MM; MFG_NAME01: MURATA; MFG_PN01: GRT155R71E104KE01D; Package Size: 0402; Package Type: SMD, MLCC; ROHS: Yes; Rated Voltage: 25V; Temp Range: -55C to +125C; Tolerance: 10%; VOLTAGE: 25V
C915 = CAP_NP: CAP CER 10uF 16V 20% X5R 0603; AGILE_PN: 150-80336; CAD_APPROVED: Yes; FPLIST: CC0603_OV,CC0603,0603_CC_NSP; HEIGHT: 1MM; MFG_NAME01: MURATA; MFG_PN01: GRM188R61C106MA73D; Package Size: 0603; Package Type: SMD; ROHS: Yes; Temp_Range: -55°C ~ 85°C; Tolerance: 20%; VOLTAGE: 16V
C916 C917 C1747 = CAP_NP: CAP CER 100uF 16V 20% X5R 1210; AGILE_PN: 150-79142; CAD_APPROVED: Yes; FPLIST: CC1210,1210_CC; HEIGHT: 2.8MM; MFG_NAME01: TAIYO YUDEN; MFG_PN01: EMK325ABJ107MM-T; Package Size: 1210; ROHS: Yes; Tolerance: 20%; VOLTAGE: 16V
C918 = CAP_NP: CAP CER 100uF 16V 20% X5R 1210; AGILE_PN: 150-79142; ASSY_OPT: DNP; CAD_APPROVED: Yes; FPLIST: CC1210,1210_CC; HEIGHT: 2.8MM; MFG_NAME01: TAIYO YUDEN; MFG_PN01: EMK325ABJ107MM-T; Package Size: 1210; ROHS: Yes; Tolerance: 20%; VOLTAGE: 16V
C921 C923 = CAP_NP: CAP CER 0.01UF 50V 10% X7R 0402; AGILE_PN: 150-30114; CAD_APPROVED: Yes; FPLIST: CC0402_25,CC0402_HD,0402_CC; HEIGHT: 0.74 MM; MFG_NAME01: KEMET; MFG_PN01: C0402C103K5RAC; ROHS: Yes; Tolerance: 10%; VOLTAGE: 50V
C1749 = CAP_NP: CAP CER 1000PF 50V 5% C0G 0402; AGILE_PN: 150-76334; CAD_APPROVED: Yes; FPLIST: CC0402_25,CC0402_HD,0402_CC; HEIGHT: 0.55MM; MFG_NAME01: MURATA; MFG_PN01: GRM1555C1H102JA01D; ROHS: Yes; Tolerance: 5%; VOLTAGE: 50V
C1750 C1751 = CAP_NP: CAP CER 22UF 16V 20% X5R 0805; AGILE_PN: 150-81221; CAD_APPROVED: Yes; FPLIST: CC0805_OV,CC0805,0805_CC; HEIGHT: 1.45MM; MFG_NAME01: TDK Corporation; MFG_PN01: C2012X5R1C226M125AC; ROHS: Yes; Tolerance: 20%; VOLTAGE: 16V
C1753 = CAP_NP: CAP CER 1000PF 50V 5% C0G 0402; AGILE_PN: 150-76334; ASSY_OPT: DNP; CAD_APPROVED: Yes; FPLIST: CC0402_25,CC0402_HD,0402_CC; HEIGHT: 0.55MM; MFG_NAME01: MURATA; MFG_PN01: GRM1555C1H102JA01D; ROHS: Yes; Tolerance: 5%; VOLTAGE: 50V
C1755 C1756 = CAP_NP: CAP CER 0.1UF 35V 10% X5R 0402; AGILE_PN: 150-78506; CAD_APPROVED: Yes; FPLIST: CC0402_25,CC0402_HD,0402_CC,capc0402_l; HEIGHT: 0.55MM; MFG_NAME01: TAIYO YUDEN; MFG_PN01: GMK105BJ104KV-F; ROHS: Yes; Temp_Range: -55°C - 85°C; Tolerance: 10%; VOLTAGE: 35V
C1792 = CAP_NP: CAP CER 1uF 16V 10% X5R 0402; AGILE_PN: 150-78973; CAD_APPROVED: Yes; FPLIST: CC0402_25,CC0402_HD,0402_CC,capc0402_l; HEIGHT: 0.55 MM; MFG_NAME01: YAGEO; MFG_PN01: CC0402KRX5R7BB105; ROHS: Yes; Tolerance: 10%; VOLTAGE: 16V
D1705 = LED: LED GRN SGL 25MA SMT 0603; AGILE_PN: 370-76672; CAD_APPROVED: Yes; HEIGHT: 0.8 MM; MFG_NAME01: DIALIGHT; MFG_PN01: 598-8070-107F; ROHS: Yes; VOLTAGE: 2V
D1706 = LED: LED OR SGL 20MA 0603; AGILE_PN: 370-76572; CAD_APPROVED: Yes; HEIGHT: 0.28MM; MFG_NAME01: KINGBRIGHT; MFG_PN01: APG1608SEKC/T; ROHS: Yes; Rated Voltage: 2V; Temp Range: -40°C to +85°C; Temp_Range: -40°C to +85°C; VOLTAGE: 2v
J1707 = CON_67_FEMALE_RA_B: CON 67 PCIE M.2 KEY-E RA SMT 0.5MM SP 270H AU; 3D_Mechanical_Footprint_File: ftp://fcl.am.freescale.net/ALLEGRO/step/con67_0p5_type-e_22x7p3_ra_270h.STEP; AGILE_PN: 211-81337; CAD_APPROVED: Yes; HEIGHT: 6.85MM; MFG_NAME01: LOTES CO LTD; MFG_PN01: APCI0452-P001A; Package Size: 22.0 x 7.3 x 6.85 mm; Package Type: SMD/SMT; ROHS: Yes
L1705 = INDUCTOR: IND PWR 0.47uH@1MHZ 4.7A 20% SMT; AGILE_PN: 180-78647; CAD_APPROVED: Yes; HEIGHT: 1.2MM; MFG_NAME01: Shenzhen Sunlord Electronics Co., Ltd; MFG_PN01: WPN252012ER47MT; PART_TYPE: INDUCTOR\POWER; ROHS: Yes; TOL: 20%; Temp_Range: -40°C to +125°C; Tolerance: 20%
Q901 Q902 = NX3008NBKW_SOT323: TRAN NMOS SW 30V 350mA AEC-Q101 SC-70; AGILE_PN: 480-79736; CAD_APPROVED: Yes; HEIGHT: 1.1MM; MFG_NAME01: NEXPERIA; ROHS: Yes
R432 R433 = RES: RES MF ZERO OHM 1/8W -- AEC-Q200 0402; AGILE_PN: 470-82894; ASSY_OPT: DNP; CAD_APPROVED: Yes; FPLIST: rc0402_25,rc0402_hd,0402_cc; HEIGHT: 0.4 MM; MFG_NAME01: VISHAY; MFG_PN01: RCC04020000Z0ED; Package Size: 0402 [1005 Metric]; Package Type: SMD/SMT; ROHS: Yes; Temp Range: -55 °C to +155 °C
R741 R742 R751 R752 = RES: RES MF ZERO OHM 1/8W -- AEC-Q200 0402; AGILE_PN: 470-82894; CAD_APPROVED: Yes; FPLIST: rc0402_25,rc0402_hd,0402_cc; HEIGHT: 0.4 MM; MFG_NAME01: VISHAY; MFG_PN01: RCC04020000Z0ED; Package Size: 0402 [1005 Metric]; Package Type: SMD/SMT; ROHS: Yes; Temp Range: -55 °C to +155 °C
R743 = RES: RES MF 56K 1/16W 5% 0402; AGILE_PN: 470-75628; CAD_APPROVED: Yes; FPLIST: RC0402_25,RC0402_HD,0402_CC; HEIGHT: 0.45MM; MFG_NAME01: BOURNS; MFG_PN01: CR0402-JW-563GLF; ROHS: Yes; Tolerance: 5%
R744 = RES: RES MF 47K 1/16W 5% 0402; AGILE_PN: 470-75559; CAD_APPROVED: Yes; FPLIST: RC0402_25,RC0402_HD,0402_CC; HEIGHT: 0.40 MM; MFG_NAME01: BOURNS; MFG_PN01: CR0402-JW-473GLF; ROHS: Yes; Tolerance: 5%
R902 = RES: RES MF 187K 1/16W 1% 0402; AGILE_PN: 470-31090; CAD_APPROVED: Yes; FPLIST: RC0402_25,RC0402_HD,0402_CC; HEIGHT: 0.40 MM; MFG_NAME01: WALSIN TECHNOLOGY CORP.; MFG_PN01: WR04X1873FTL; ROHS: Yes; Temp_Range: -55C to +155C; Tolerance: 1%
R903 R950 = RES: RES MF 1.0K 1/16W 5% 0402; AGILE_PN: 470-75555; ASSY_OPT: DNP; CAD_APPROVED: Yes; FPLIST: RC0402_25,RC0402_HD,RC0402_X2,0402_CC,CAPC0402_L; HEIGHT: 0.41mm; MFG_NAME01: VISHAY INTERTECHNOLOGY; MFG_PN01: CRCW04021K00JNED; ROHS: Yes; Tolerance: 5%
R922 R1790 R1791 = RES: RES MF 1.0K 1/16W 5% 0402; AGILE_PN: 470-75555; CAD_APPROVED: Yes; FPLIST: RC0402_25,RC0402_HD,RC0402_X2,0402_CC,CAPC0402_L; HEIGHT: 0.41mm; MFG_NAME01: VISHAY INTERTECHNOLOGY; MFG_PN01: CRCW04021K00JNED; ROHS: Yes; Tolerance: 5%
R957 = RES: RES MF 100 OHM 1/16W 5% 0402; AGILE_PN: 470-82142; CAD_APPROVED: Yes; FPLIST: RC0402_25,RC0402_HD,RC0402_X2,0402_CC; HEIGHT: 0.45MM; MFG_NAME01: SMEC; MFG_PN01: RC73L2Z101JTF; ROHS: Yes; Temp Range: -55°C to +175°C; Tolerance: 5%
R1782 = RES: RES MF 41.2K 1/10W 1% AEC-Q200 0402; AGILE_PN: 470-81721; CAD_APPROVED: Yes; FPLIST: RC0402_25,RC0402_HD,0402_CC; HEIGHT: 0.40 MM; MFG_NAME01: KOA SPEER; MFG_PN01: RK73H1ETTP4122F; ROHS: Yes; Temp_Range: -55C to +155C; Tolerance: 1%
R1812 = RES: RES MF 120K 1/10W 1% AEC-Q200 0402; AGILE_PN: 470-31069; CAD_APPROVED: Yes; FPLIST: RC0402_25,RC0402_HD,0402_CC; HEIGHT: 0.40 MM; MFG_NAME01: KOA SPEER; MFG_PN01: RK73H1ETTP1203F; ROHS: Yes; Temp Range: -55C to +155C; Tolerance: 1%
TP901 = T_POINT_R: TEST POINT PAD .035 SMT, no part to order; AGILE_PN: 510-75618; CAD_APPROVED: Yes; HEIGHT: 0.1MM; ROHS: Yes
U904 = 74AVC4T3144_12P_A: IC BUF DUAL 4BIT NON-INVERT TS 0.8-3.6V XQFN12; 3D_Mechanical_Footprint_File: ftp://fcl.am.freescale.net/ALLEGRO/step/xqfn12_0p4_1p8x2p1.step; AGILE_PN: 315-82443; CAD_APPROVED: Yes; HEIGHT: 0.5MM; MFG_NAME01: Nexperia; MFG_PN01: 74AVC4T3144GU12X; ROHS: Yes; Supply Voltage: 0.8-3.6V; Temp Range: -40°C to 125°C; VOLTAGE: 0.8-3.6V
U905 = TXB0304RUT_12P_B: IC VXLTR BIDIR DUAL PORTS 4BIT 0.9-3.6V UQFN12; 3D_Mechanical_Footprint_File: ftp://fcl.am.freescale.net/ALLEGRO/step/uqfn12_1p7x2mm.STEP; AGILE_PN: 312-80888; ASSY_OPT: DNP; CAD_APPROVED: Yes; HEIGHT: 0.55 MM; MFG_NAME01: TEXAS INSTRUMENTS; ROHS: Yes; VOLTAGE: 0.9-3.6V
U906 = TXB0304RUT_12P_B: IC VXLTR BIDIR DUAL PORTS 4BIT 0.9-3.6V UQFN12; 3D_Mechanical_Footprint_File: ftp://fcl.am.freescale.net/ALLEGRO/step/uqfn12_1p7x2mm.STEP; AGILE_PN: 312-80888; CAD_APPROVED: Yes; HEIGHT: 0.55 MM; MFG_NAME01: TEXAS INSTRUMENTS; ROHS: Yes; VOLTAGE: 0.9-3.6V
U908 = NTS0104GU12_12P: IC DUAL VXLTR XCVR 4BIT 1.65-3.6/2.3-5.5V XQFN12; 3D_Mechanical_Footprint_File: http://fcl.am.freescale.net/ALLEGRO/step/xqfn12_0p4_1p8x2p1.step; AGILE_PN: 312-82046; ASSY_OPT: DNP; CAD_APPROVED: Yes; HEIGHT: 0.5MM; MFG_NAME01: NXP SEMICONDUCTORS; ROHS: Yes; Temp Range: -40 to +125C; VOLTAGE: 1.65-3.6/2.3-5.5V
U1710 = MP2147GD_QFN_11P: IC VREG BUCK 0.6V-5.5V 4A 2.8--5.5V QFN12; AGILE_PN: 315-80523; CAD_APPROVED: Yes; HEIGHT: 1MM; MFG_NAME01: MONOLITHIC POWER SYSTEMS; ROHS: Yes

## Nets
GND: BH901.1 C22.2 C23.2 C406.2 C408.2 C409.2 C410.2 C411.2 C412.2 C413.1 C414.2 C418.2 C510.2 C511.2 C512.2 C513.2 C514.2 C515.2 C516.2 C517.2 C518.2 C519.2 C520.2 C521.2 C912.2 C913.2 C914.2 C915.2 C916.2 C917.2 C918.2 C920.2 C921.2 C922.2 C923.2 C1733.2 C1734.2 C1735.2 C1736.2 C1737.1 C1738.2 C1739.2 C1740.2 C1741.2 C1742.2 C1743.2 C1744.1 C1745.2 C1746.2 C1747.2 C1748.2 C1750.2 C1751.2 C1752.2 C1754.2 C1755.2 C1756.2 C1757.2 C1792.2 D302.A(ANODE) J1101.A1(GND1) J1101.A12(GND2) J1101.B1(GND4) J1101.B12(GND3) J1101.SH1 J1101.SH2 J1101.SH3 J1101.SH4 J1707.1(GND1) J1707.7(GND2) J1707.18(GND3) J1707.33(GND5) J1707.39(GND4) J1707.45(GND6) J1707.51(GND7) J1707.57(GND8) J1707.63(GND9) J1707.69(GND10) J1707.75(GND11) Q901.2(SOURCE) Q902.2(SOURCE) R412.1 R413.1 R507.2 R508.2 R509.1 R519.2 R520.2 R521.2 R522.2 R523.2 R524.2 R525.2 R526.2 R527.2 R741.2 R742.2 R743.1 R751.2 R752.2 R954.2 R1770.2 R1771.2 R1772.2 R1781.2 R1782.2 R1812.1 U401.5(SLV_ADDR) U401.17(GND) U402.A4(GND1) U402.B2(GND2) U402.B3(GND3) U402.B4(GND4) U402.B5(GND5) U403.B1(GND) U404.2(VSS) U405.3(GND) U411.B3(GND) U411.D3(SBUEN) U502.3(GND1) U502.8(GND2) U503.3(GND1) U503.8(GND2) U904.6(GND) U905.6(GND) U906.6(GND) U908.6(GND) U1710.10(GND) U1712.41(GND) Y501.2 Y501.4 ; also on sheet 1 4 5 6 10 11 12 16 17 18 19 20 21 22 23
GND_CHASSIS: C1744.2 J501.10(GND) J501.SH1 J501.SH2 R509.2
VBUS_IN: C1735.1 R1773.2 R1774.2 ; also on sheet 10 11
VDD_1V8: C23.1 C922.1 C923.1 C1756.1 R510.1 R746.2 R951.1 R952.1 R956.2 R1767.1 R1779.1 U904.11(VCCB) U905.11(VCCB) U906.1(VCCA) U908.1(VCCA) ; also on sheet 5 6 12 16 17 18 21 22 23
VDD_3V3: C22.1 C411.1 C920.1 C921.1 C1755.1 C1792.1 L501.1 L502.1 R431.1 R505.1 R506.1 R923.1 R935.1 R950.1 R1768.1 R1775.1 R1813.1 U401.3(VDD) U904.1(VCCA) U905.1(VCCA) U906.11(VCCB) U908.11(VCCB) ; also on sheet 5 6 10 11 12 16 17 19 20 21 22 23
VDD_5V: C413.2 C1733.1 R1766.1 U401.12(VCONN_IN) U404.5(VDD) ; also on sheet 6 10 11 19 21
BYPASS1: C1737.2 U401.4(BYPASS)
DBG_ACC: TP1926.1(Pin1) U401.9(DBG_ACC)
EN_SNK: R411.2 U402.F1(EN_SNK)
EN_SRC: R410.2 U402.G1(EN_SRC)
ENET1_MDC: R503.1 ; also on sheet 20
ENET1_MDIO: R1779.2 R1780.1 ; also on sheet 20
ENET1_nINT: R505.2 U1712.31(~{INT}/~{PME}) ; also on sheet 12
ENET1_nRST: R506.2 U1712.12(~{PHYRST}) ; also on sheet 12
ENET1_RD0: R517.2 R526.1 U1712.25(RXD0/RXDLY) ; also on sheet 20
ENET1_RD1: R518.2 R527.1 U1712.24(RXD1/TXDLY) ; also on sheet 20
ENET1_RD2: R514.2 R522.1 U1712.23(RXD2/PLLOFF) ; also on sheet 20
ENET1_RD3: R515.2 R523.1 U1712.22(RXD3/PHYAD0) ; also on sheet 20
ENET1_RX_CTL: R525.1 U1712.26(RXCTL/PHYAD2) ; also on sheet 20
ENET1_RXC: C519.1 R516.2 R524.1 U1712.27(RXC/PHYAD1) ; also on sheet 20
ENET1_TD0: U1712.18(TXD0) ; also on sheet 20
ENET1_TD1: U1712.17(TXD1) ; also on sheet 20
ENET1_TD2: U1712.16(TXD2) ; also on sheet 20
ENET1_TD3: U1712.15(TXD3) ; also on sheet 20
ENET1_TX_CTL: U1712.19(TXCTL) ; also on sheet 20
ENET1_TXC: U1712.20(TXC) ; also on sheet 20
ETH1_10/100M_Link/Active: J501.13 R504.1
ETH1_1000M_Link/Active: J501.11 R507.1 R529.1
ETH1_AVDD1V0: C515.1 C516.1 C517.1 C518.1 R530.2 U1712.3(AVDD09_1) U1712.8(AVDD09_2) U1712.38(AVDD09_3)
ETH1_AVDD3V3: C1742.1 C1743.1 L502.2 U1712.11(AVDD33_1) U1712.40(AVDD33_2)
ETH1_CLK125_OUT: TP1933.1(Pin1) U1712.35(CLKOUT)
ETH1_CT: C1738.1 J501.1(CT)
ETH1_DVDD1V0: C513.1 C514.1 R531.2 U1712.21(DVDD09)
ETH1_DVDD3V3: C1739.1 C1740.1 L501.2 R512.1 R513.1 R529.2 U1712.29(DVDD33)
ETH1_LED0/CFG_EXT: R504.2 R512.2 R519.1 U1712.32(CFG_EXT/LED0)
ETH1_LED1/CFGLDO0: C520.1 J501.14 R521.1 U1712.33(CFG_LDO0/LED1)
ETH1_LED2/CFGLDO1: C521.1 J501.12 R513.2 R520.1 U1712.34(CFG_LDO1/LED2)
ETH1_TRX0_N: J501.3(TRD1-) U503.2(CH2) U503.9(NC3) U1712.2(MDIN0)
ETH1_TRX0_P: J501.2(TRD1+) U503.1(CH1) U503.10(NC4) U1712.1(MDIP0)
ETH1_TRX1_N: J501.5(TRD2-) U503.5(CH4) U503.6(NC1) U1712.5(MDIN1)
ETH1_TRX1_P: J501.4(TRD2+) U503.4(CH3) U503.7(NC2) U1712.4(MDIP1)
ETH1_TRX2_N: J501.7(TRD3-) U502.2(CH2) U502.9(NC3) U1712.7(MDIN2)
ETH1_TRX2_P: J501.6(TRD3+) U502.1(CH1) U502.10(NC4) U1712.6(MDIP2)
ETH1_TRX3_N: J501.9(TRD4-) U502.5(CH4) U502.6(NC1) U1712.10(MDIN3)
ETH1_TRX3_P: J501.8(TRD4+) U502.4(CH3) U502.7(NC2) U1712.9(MDIP3)
ETH1_VDD1V0: C511.1 C512.1 R530.1 R531.1 U1712.30(LDO_OUT)
ETH1_VDDIO: C1745.1 C1746.1 R510.2 R514.1 R515.1 R516.1 R517.1 R518.1 U1712.28(DVDD_RG)
ETH1_XTALI: C510.1 R511.2 U1712.36(XTAL_IN) Y501.3
ETH1_XTALO: C1741.1 R511.1 U1712.37(XTAL_OUT/_EXT_CLK) Y501.1
EXT1_PWREN: R922.1 ; also on sheet 12
FRS_EN: U401.1(FRS_EN) U402.B6(FRS_EN)
I2C1_SCL: R433.1 ; also on sheet 6 10 12 17 20 21
I2C1_SCLL: J1707.60(I2C_CLK) R930.2 ; also on sheet 17
I2C1_SDA: R432.1 ; also on sheet 6 10 12 17 20 21
I2C1_SDAL: J1707.58(I2C_DATA) R931.2 ; also on sheet 17
I3C_TEMP_nINT: R744.2 ; also on sheet 12
i.MX_SPI_CLK/UART_RTSO: R944.2 U905.8(B3) U906.4(A3)
i.MX_SPI_CS/UART_TXD: R938.2 R945.2 U905.10(B1) U906.2(A1)
i.MX_SPI_MISO/UART_RXD: R943.2 U905.7(B4) U906.5(A4)
i.MX_SPI_MOSI/UART_CTSI: R941.2 R942.2 U905.9(B2) U906.3(A2)
ILIM_5V_VBUS: TP1927.1(Pin1) U401.6(ILIM_5V_VBUS)
LD_I2C_SCL: R420.1 U402.B1(SCL)
LD_I2C_SDA: R421.1 R434.1 U402.C1(SDA)
LD_nFLT: R1775.2 R1776.1 U401.11(FAULT_N)
LD_nINT: R1776.2 U402.D1(~{INT})
LS_OE: R935.2 R1812.2 U905.12(OE) U906.12(OE)
M2_LED1#: D1705.C(CATHODE) J1707.6(~{LED1})
M2_LED2#: D1706.C(CATHODE) J1707.16(~{LED2})
M2_nALERT: R932.2 R936.2 ; also on sheet 12
M2_nDIS1: J1707.56(~{W_DISABLE1}) R903.1 ; also on sheet 12
M2_nDIS2: J1707.54(~{W_DISABLE2}) Q902.1(GATE) R953.1 ; also on sheet 12
M2_nRST: J1707.52(~{PERST0}) ; also on sheet 12
M2_PCM_CLK: J1707.8(I2S_SCK) R946.2
M2_PCM_IN: J1707.12(I2S_SD_IN) R949.2
M2_PCM_OUT: J1707.14(I2S_SD_OUT) R948.2
M2_PCM_SYNC: J1707.10(I2S_WS) R947.2
M2_PWRON: C1754.1 R903.2 R922.2 R950.2 R1781.1 U1710.5(EN)
M2_SD_nWAKE: J1707.21(~{SDIO_WAKE}) R1793.2 TP918.1(Pin1)
M2_UART_nWAKE: J1707.20(~{UART_WAKE}) R924.2 ; also on sheet 12
M2_USB_DN: J1707.5(USB_D-) TP1935.1(Pin1)
M2_USB_DP: J1707.3(USB_D+) TP1934.1(Pin1)
PCIE_CLKN: J1707.49(REFCLK_N0) TP909.1(Pin1)
PCIE_CLKP: J1707.47(REFCLK_P0) TP908.1(Pin1)
PCIE_nCLKREQ: J1707.53(~{CLKREQ0}) TP910.1(Pin1)
PCIE_nWAKE: J1707.55(~{PEWAKE0}) R917.2 TP920.1(Pin1)
PCIE_RXN: J1707.43(PER_N0) TP907.1(Pin1)
PCIE_RXP: J1707.41(PER_P0) TP906.1(Pin1)
PCIE_TXN: J1707.37(PET_N0) TP905.1(Pin1)
PCIE_TXP: J1707.35(PET_P0) TP911.1(Pin1)
PMIC_32K_OUT: R958.2 ; also on sheet 1 17
RTC_CLKO: R959.2 ; also on sheet 19
SAI1_RXD0: R909.1 ; also on sheet 20
SAI1_TXC: R1784.1 ; also on sheet 20
SAI1_TXD0: R1786.1 ; also on sheet 20 23
SAI1_TXFS: R1785.1 ; also on sheet 20 23
SD3_CLK: J1707.9(SDIO_CLK) TP912.1(Pin1) ; also on sheet 20
SD3_CMD: J1707.11(SDIO_CMD) R952.2 TP913.1(Pin1) ; also on sheet 20
SD3_DATA0: J1707.13(SDIO_DATA0) R951.2 TP914.1(Pin1) ; also on sheet 20
SD3_DATA1: J1707.15(SDIO_DATA1) TP1936.1(Pin1) ; also on sheet 20
SD3_DATA2: J1707.17(SDIO_DATA2) TP1937.1(Pin1) ; also on sheet 20
SD3_DATA3: J1707.19(SDIO_DATA3) TP917.1(Pin1) ; also on sheet 20
SD3_nRST: J1707.23(~{SDIO_RST}) TP919.1(Pin1) ; also on sheet 12
SD3_nWAKE: R923.2 R1793.1 ; also on sheet 12
SPI3_CLK: U905.4(A3) U906.8(B3) ; also on sheet 12
SPI3_CS0: U905.2(A1) U906.10(B1) ; also on sheet 12
SPI3_MISO: U905.5(A4) U906.7(B4) ; also on sheet 12
SPI3_MOSI: U905.3(A2) U906.9(B2) ; also on sheet 12
SUSCLK: J1707.50(SUSCLK) R919.1
TCPC1_nINT: R431.2 U401.10(ALERT_N) ; also on sheet 12
UART5_CTSI: J1707.34(UART_CTS) ; also on sheet 1
UART5_RTSO: J1707.36(UART_RTS) ; also on sheet 1
UART5_RXD: J1707.22(UART_RXD) ; also on sheet 1
UART5_TXD: J1707.32(UART_TXD) ; also on sheet 1
USB1_CC1: U401.13(CC1) U411.A2(CC1)
USB1_CC2: U401.14(CC2) U411.B2(CC2) U411.C1(CON_SBU1) U411.C2(SBU1)
USB1_DN: U403.C1(CH1_OUT+) ; also on sheet 19 20
USB1_DP: U403.C2(CH1_OUT-) ; also on sheet 19 20
USB1_ID: R1767.2 TP1924.1(Pin1) ; also on sheet 20
USB1_VBUS_3V3: R1768.2 U404.1(VOUT) ; also on sheet 20
USB1_VBUS_IN: C407.2 R1773.1 R1774.1 TP1925.1(Pin1) U402.C6(VCHG1) U402.D6(VCHG2) U402.E6(VCHG3) U402.F6(VCHG4) U402.G6(VCHG5)
USB_I2C_SCL: R420.2 R1777.2 ; also on sheet 10 19
USB_I2C_SDA: R421.2 R1778.2 ; also on sheet 10 19
USB_PD_VBUS_F: D401.A(ANODE) ; also on sheet 10
USBC_CC1: J1101.A5(CC1) TP1928.1(Pin1) U411.A1(CON_CC1)
USBC_CC2: J1101.B5(CC2) TP1929.1(Pin1) U411.B1(CON_CC2)
USBC_DN: J1101.A7(DN1) J1101.B7(DN2) U403.A1(CH1_IN+)
USBC_DP: J1101.A6(DP1) J1101.B6(DP2) U403.A2(CH1_IN-)
USBC_EN_SNK1: R411.1 U401.2(EN_SNK1)
USBC_EN_SRC1: R410.1 U401.16(EN_SRC)
USBC_I2C_SCL: R1777.1 U401.8(I2C_SCL)
USBC_I2C_SDA: R1778.1 U401.7(I2C_SDA)
USBC_SBU1: J1101.A8(SBU1) TP1930.1(Pin1)
USBC_SBU2: J1101.B8(SBU2) TP1931.1(Pin1)
USBC_VBUS: F401.1 J1101.A4(VBUS1) J1101.A9(VBUS2) J1101.B4(VBUS4) J1101.B9(VBUS3) ; also on sheet 19
USBC_VBUS_F: C1734.1 D402.A(ANODE) F401.2 R360.1 R1769.1 R1770.1 U401.15(VBUS) U402.C2(VBUS1) U402.C3(VBUS2) U402.C4(VBUS3) U402.C5(VBUS4) U402.D4(VBUS5) U402.D5(VBUS6) U402.E4(VBUS7) U402.E5(VBUS8) U402.F4(VBUS9) U402.F5(VBUS10) U402.G4(VBUS11) U402.G5(VBUS12)
VEN_SPI_CLK/UART_RTSO: J1707.42(VEN_DEF3) R944.1
VEN_SPI_FRM/UART_CTSI: R941.1 R945.1 R957.2
VEN_SPI_RXD/UART_SIN: J1707.40(VEN_DEF2) R943.1
VEN_SPI_TXD/UART_SOUT: J1707.38(VEN_DEF1) R938.1 R942.1
VLDO1_3V3: C410.1 U402.A5(VLDO)
VLDO_3V3: C408.1 C412.1 C418.1 U402.A1(VDD) U405.1(OUT) U411.A3(VSYS) ; also on sheet 10 19
VPCIe_3V3: C912.1 C913.1 C914.1 C915.1 C916.1 C917.1 C918.1 C1749.1 C1750.1 C1751.1 C1752.1 C1753.2 C1757.1 J1707.2(3V3_1) J1707.4(3V3_2) J1707.72(3V3_3) J1707.74(3V3_4) L1705.2 R902.1 R917.1 R918.1 R924.1 R936.1 R1790.2 R1791.2 U1710.2(OUT) ; also on sheet 21
VSYS_5V: C406.1 C1736.1 C1747.1 C1748.1 R1783.1 U402.D2(V5V_1) U402.D3(V5V_5) U402.E2(V5V_2) U402.E3(V5V_6) U402.F2(V5V_3) U402.F3(V5V_7) U402.G2(V5V_4) U402.G3(V5V_8) U1710.8(VIN1) U1710.11(VIN2) ; also on sheet 11 17 19
N115742694: R1766.2 R1772.1 U404.4(IN_INV)
N115742746: D302.C(CATHODE) R360.2 R1769.2 R1771.1 U404.3(IN_NON-INV)
N115743253: C407.1 U402.A6(CAP2)
N115743279: C409.1 U402.A3(CAP1)
N115743338: R412.2 U402.A2(~{EN})
N115743354: R413.2 R434.2 U402.E1(ADDR)
N115743625: C414.1 D401.C(CATHODE) D402.C(CATHODE) U405.2(IN)
N115744998: TP1932.1(Pin1) U411.C3(FLAG)
N115747363: R1780.2 U1712.14(MDIO)
N115747381: R503.2 U1712.13(MDC)
N115751791: L1705.1 U1710.1(SW1) U1710.9(SW2)
N115751937: C1749.2 R902.2 R1782.1 U1710.3(FB)
N115752033: R1783.2 U1710.6(MODE/VCON)
N115752037: C1753.1 U1710.4(RAMP)
N115752085: TP901.1(TP) U1710.7(PG)
N115752389: R1784.2 U904.2(A1)
N115752394: R946.1 U904.10(YB1)
N115752439: R1785.2 U904.3(A2)
N115752462: R947.1 U904.9(YB2)
N115752527: R1786.2 U904.4(A3)
N115752535: R948.1 U904.8(YB3)
N115752568: R909.2 U904.5(YA4)
N115752570: R949.1 U904.7(B4)
N115753009: D1705.A(ANODE) R1790.1
N115753214: D1706.A(ANODE) R1791.1
N115753489: Q901.3(DRAIN) R918.2 R919.2
N115753655: Q901.1(GATE) R958.1 R959.1
N115753665: J1707.62(~{ALERT}) R932.1
N115863629: R508.1 U1712.39(RSET)
N115991118: Q902.3(DRAIN) R953.2 R954.1 R1813.2 U904.12(~{OE})
N116165116: J1707.64(RESERVED) R956.1 R957.1
N116481485: R930.1 U908.2(A1)
N116482975: R931.1 U908.3(A2)
N116484883: R743.2 R744.1 R746.1 U908.12(OE)
N116485241: R432.2 U908.9(B2)
N116561239: R433.2 U908.10(B1)
N116562204: R741.1 U908.8(B3)
N116562207: R751.1 U908.7(B4)
N116562556: R742.1 U908.4(A3)
N116562559: R752.1 U908.5(A4)

Not connected (* = marked no-connect by the designer): J1101 A2(SSTXP1)* A3(SSTXN1)* A10(SSRXN2)* A11(SSRXP2)* B2(SSTXP2)* B3(SSTXN2)* B10(SSRXN1)* B11(SSRXP1)*; J1707 44(COEX3)* 46(COEX2)* 48(COEX1)* 59(PET_P1)* 61(PET_N1)* 65(PER_P1)* 66(~{PERST1})* 67(PER_N1)* 68(~{CLKREQ1})* 70(~{PEWAKE1})* 71(REFCLK_P1)* 73(REFCLK_N1)*; U411 D1(CON_SBU2)* D2(SBU2)*

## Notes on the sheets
sheet 7
- M.2 KEY-E
- NOTE: backup for U905 due to compatible part design,
  TOP/BOT symmetric placement on PCB
- # 3.3V/4A
- VCC(A) <= VCC(B)
- #Second SRC for LS：
- TXB0104QRUTRQ1
- TXB0304RUTR
- NTB0104GU12
- FXLA0104QFX
- LS
- Ru
- NLSX3014MUTAG
- PI4ULS3V304A
- Vfb=0.6V
- Vout = (Rd+Ru) * Vfb / Rd
- Rd
- # Discharge Resistor: 150 OHM
- MODE:
    >1.2V PWM
    <0.4V PFM
- #GPIO_IO08
- #GPIO_IO10
- 2230
- #GPIO_IO11
- #GPIO_IO09
- LS
- #BUF / LS replacement
- 74AVC4T3144
- <nOE>
- TXBN0304RUTR
- <nOE>
- #BUF / LS replacement
- TXB0304RUTR
- <OE>
- 74AVC4T3144
- <nOE>
- TXB0304RUTR
- <OE>
- M.2 / NGFF
- 2230/2242/2280: PCIe for SSD
- RSV for Modem/WiFi/BT/SSD
- SPI
- 2230: PCIe/USB/SDIO/UART/PCM/I2C for WiFi
- DIM:  2230/2242/2280
- # Current Consumption Limit Peak: 2500mA
- WLAN STAT
- #PCM: MASTER/SLAVE SUPPORT
- i
- o
- UART
- BT STAT
- o
- o
- o
- i
- o
- i
- o
- #VEN_DEF/RSV: 1.8V DOMAIN, SPI/UART for IEEE802.15.4
- i
- i/o
- i
- o
- i
- Level Shifter
- # PIN64 has been defined as VIO-1.8V from M.2 4.0
  SPEC, R957 kept as the compatible design
- APCI0452-P001A
- H:6.85MM
- M.2 SCREW
- # Ultra height reserved for M.2 expansion adapter board
- # DEFAULT M.2 MODULE:
- NXP IW61X
- LS
- Key ID
- Pin
- Interface
- Key Definition
- A
  B
  C
  D
  E
  F
  G
  H
  J
  K
  L
  M
- 8-15
  12-19
  16-23
  20-27
  24-31
  28-35
  39-46
  43-50
  47-54
  51-58
  55-62
  59-66
- 2x PCIe x1 / USB 2.0 / I2C / DP x4
  PCIe x2 / SATA / USB 2.0 / USB 3.1 Gen1 / HSIC / SSIC / Audio / UIM / I2C / SMBus
  PCIe/M-PCIe  / USB 2.0 / USB 3.1 Gen1 / SSIC / I2C-SlimBUS / UIM / ANTCTL
  Reserved for Future Use (RFU)
  2x PCIe x1 / USB 2.0 / I2C / SDIO / UART / PCM
  Future Memory Interface (FMI)
  Not Used for M.2; for Custom/Non-Standard Apps
  Reserved for Future Use (RFU)
  Reserved for Future Use (RFU)
  Reserved for Future Use (RFU)
  Reserved for Future Use (RFU)
  PCIe x4 / SATA / SMBus
- Display Port Based Connectivity
  WWAN/SSD/Others Primary Key
  WWAN Key
  RFU
  SDIO Based Connectivity
  Future Memory Interface
  Generic (Not used for M.2)
  RFU
  RFU
  RFU
  RFU
  SSD 4 Lane PCIe
- i.MX93 GPIO8-11
- #GPIO_IO08
- #SPI3_CS
- #UART7_TXD
- #GPIO_IO09
- #SPI3_MISO
- #UART7_RXD
- #GPIO_IO10
- #SPI3_MOSI
- #UART7_CTS <I>
- #GPIO_IO11
- #SPI3_CLK
- #UART7_RTS <O>
- IW61X GPIO12-15
- #GPIO_IO15
- #SPI_TXD
- #UART2_SOUT
- #GPIO_IO14
- #SPI_RXD
- #UART2_SIN
- #GPIO_IO13
- #SPI_FRM
- #UART2_RTS <O>
- #GPIO_IO12
- #SPI_CLK
- #UART2_CTS <I>
sheet 8
- RGMII 10/100/1000Mbps Ethernet
- 10/100Mb/s Link / Active
- Z:100 OHM
- 1000Base-T <first pair>/10Base-T & 100Base-TX <transmit pair>
- 1000Base-T <second pair>/10Base-T & 100Base-TX <receive pair>
- Z:100 OHM
- 1000Base-T <third pair>
- 1000Base-T <fourth pair>
- O/LI/PD
- LED0: 10Mbps
- O/LI/PU
- LED1: 100Mbps
- O/LI/PD
- LED2: 1000Mbps
- 1 Gb/s Link / Active
- 3.3V IO
- 3.3V IO
- Ethernet IO Voltage,
  default = 1.8 V
  Internal.
- ESD protection
- Power-on Strapping Pins CFG
- RGMII Power Source
- CFG_EXT
- CFG_LDO[1:0]
- External 3.3V
- 1
- 00
- External 2.5V
- 1
- 01
- External 1.8V
- 1
- 10
- External 1.5V
- 1
- 11
- Internal 2.5V
- 0
- 01
- Internal 1.8V(Default)
- 0
- 10
- Internal 1.5V
- 0
- 11
- PHY Address
- PHYAD[2:0]
- 1
- 001
- 2
- 010
- # Pull-up for additional 2ns delay to
  TXC/RXC for data latching.
- # Pull-up to disable PLL @ ALDPS mode.
- EMI Filter Reserved
sheet 9
- USB TYPE-C
- For discharge
- #VBUS > 3.7V ->  H
- #VBUS < 3.7V ->  L
- VBUS DET
- De-bounce
- PWR SW OFF
- PWR SW ON
- Reboot
- #Set to 3.4A I2C CTRL
- # Use Always On Power(with VBUS), aviod entering Dead Battery Mode.
- OD
- I/OD
- #I2C ADDR: 0b'11100[01]x
- O
- Always ON LDO
- O
- #default "L"
- # This LDO is used for preventing the Ld SW
  NX20P3483UK enter into dead battery mode.
- O
- O/OD
- default "UFP" mode
- #I2C ADDR: 0b'1010000X
- connected pin ALERT_N of U401 and pin INT of U801 via net TCPC1_nINT in this design due to MPU GPIO limitation.
  such design may triger IRQ storm and I2C bus stick in very low rate when keep VBUS of U401 connects to PC and power cycle the board.
  for end-user case shall not share the INT for both U401 and U801.
- Z:90 OHM
- Z:90 OHM
- #C1 C2 PIN used for layout convenient
- CC OVP
